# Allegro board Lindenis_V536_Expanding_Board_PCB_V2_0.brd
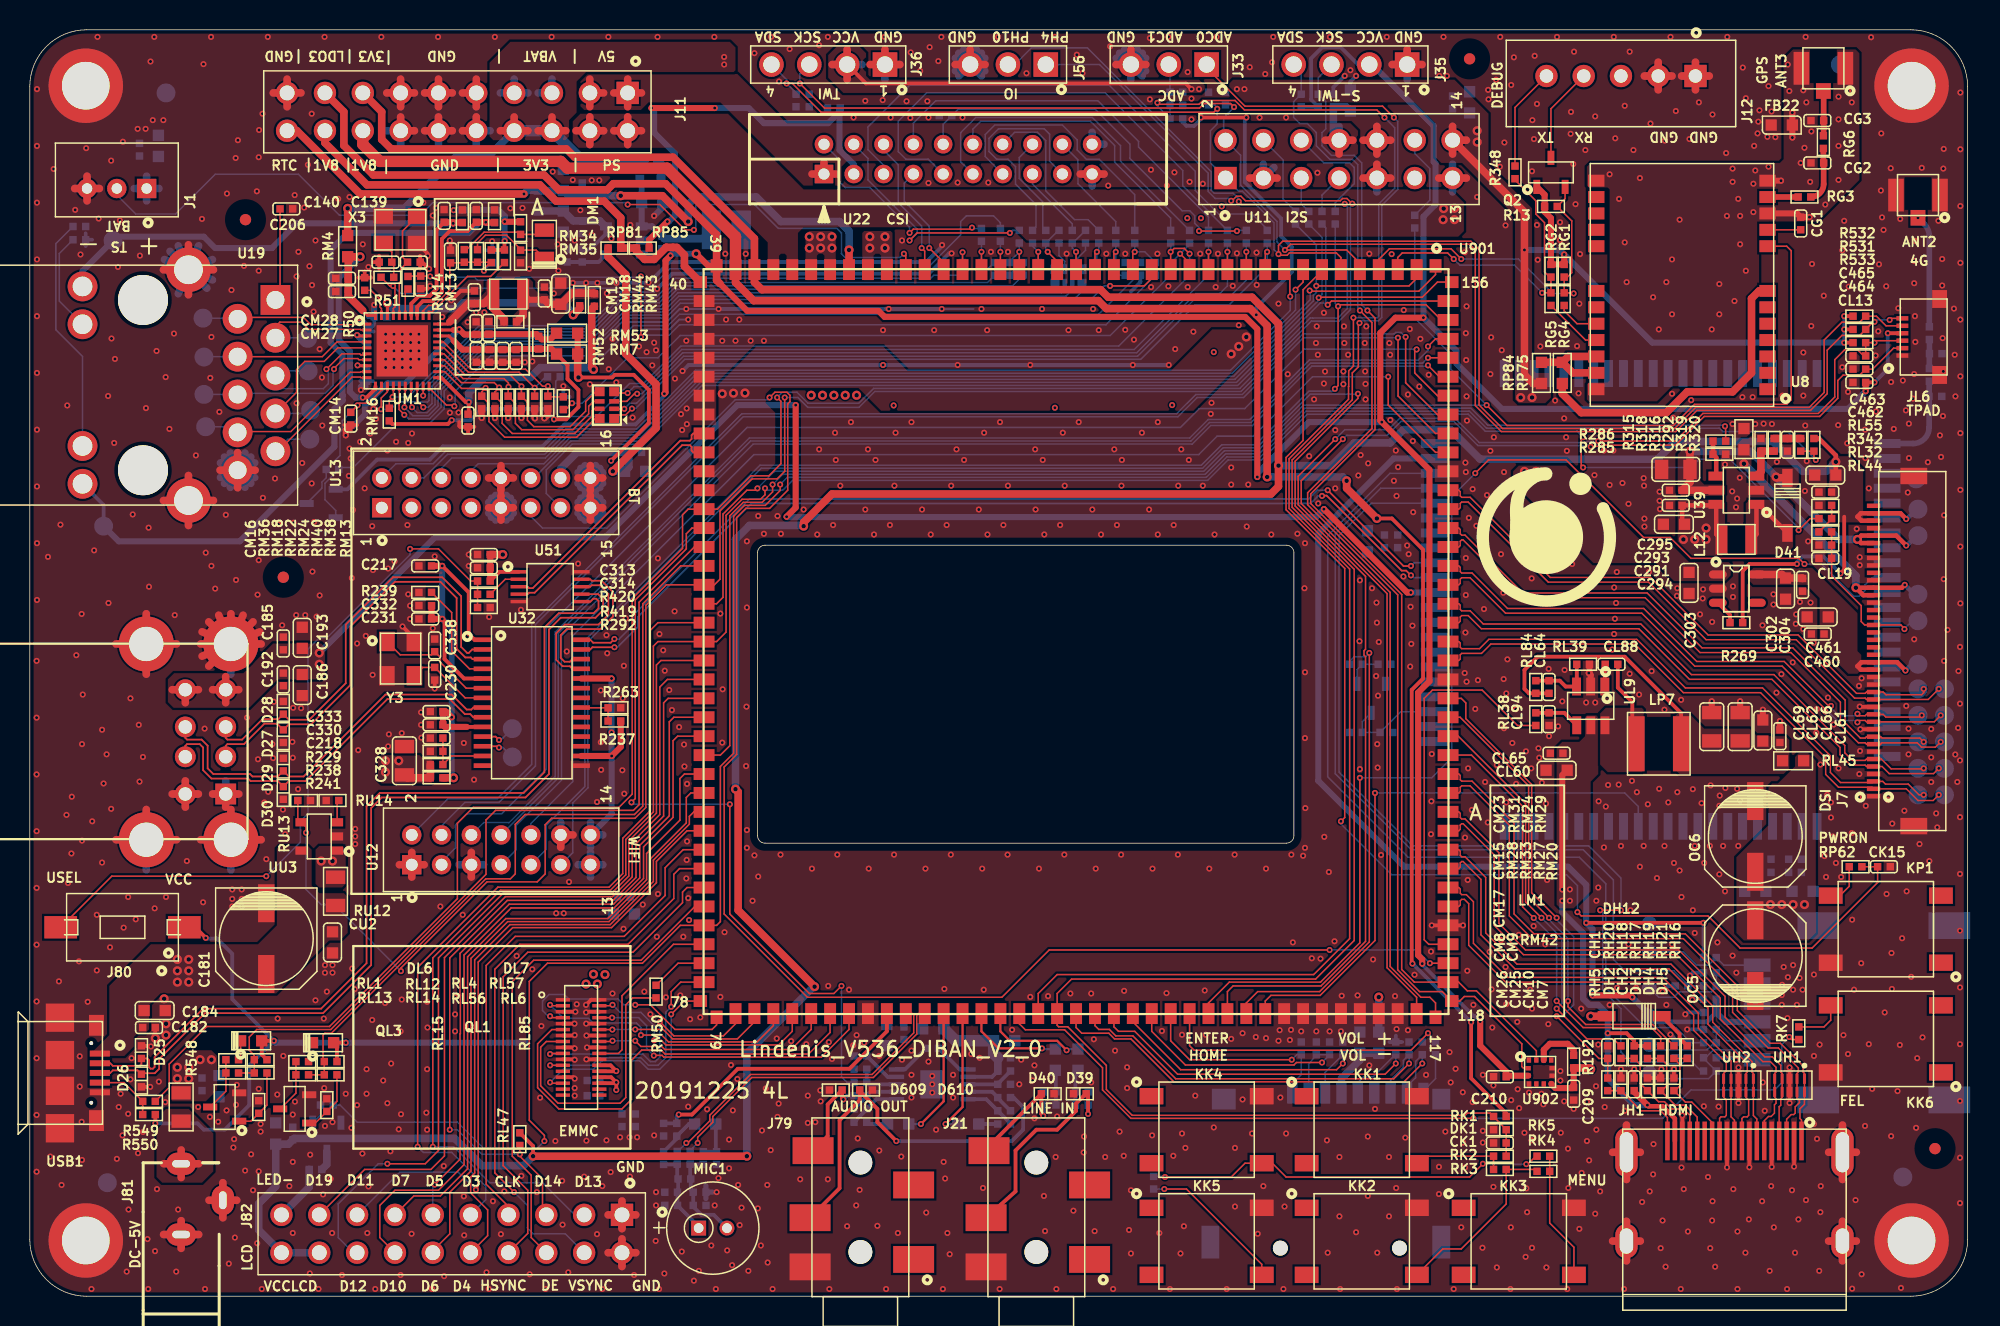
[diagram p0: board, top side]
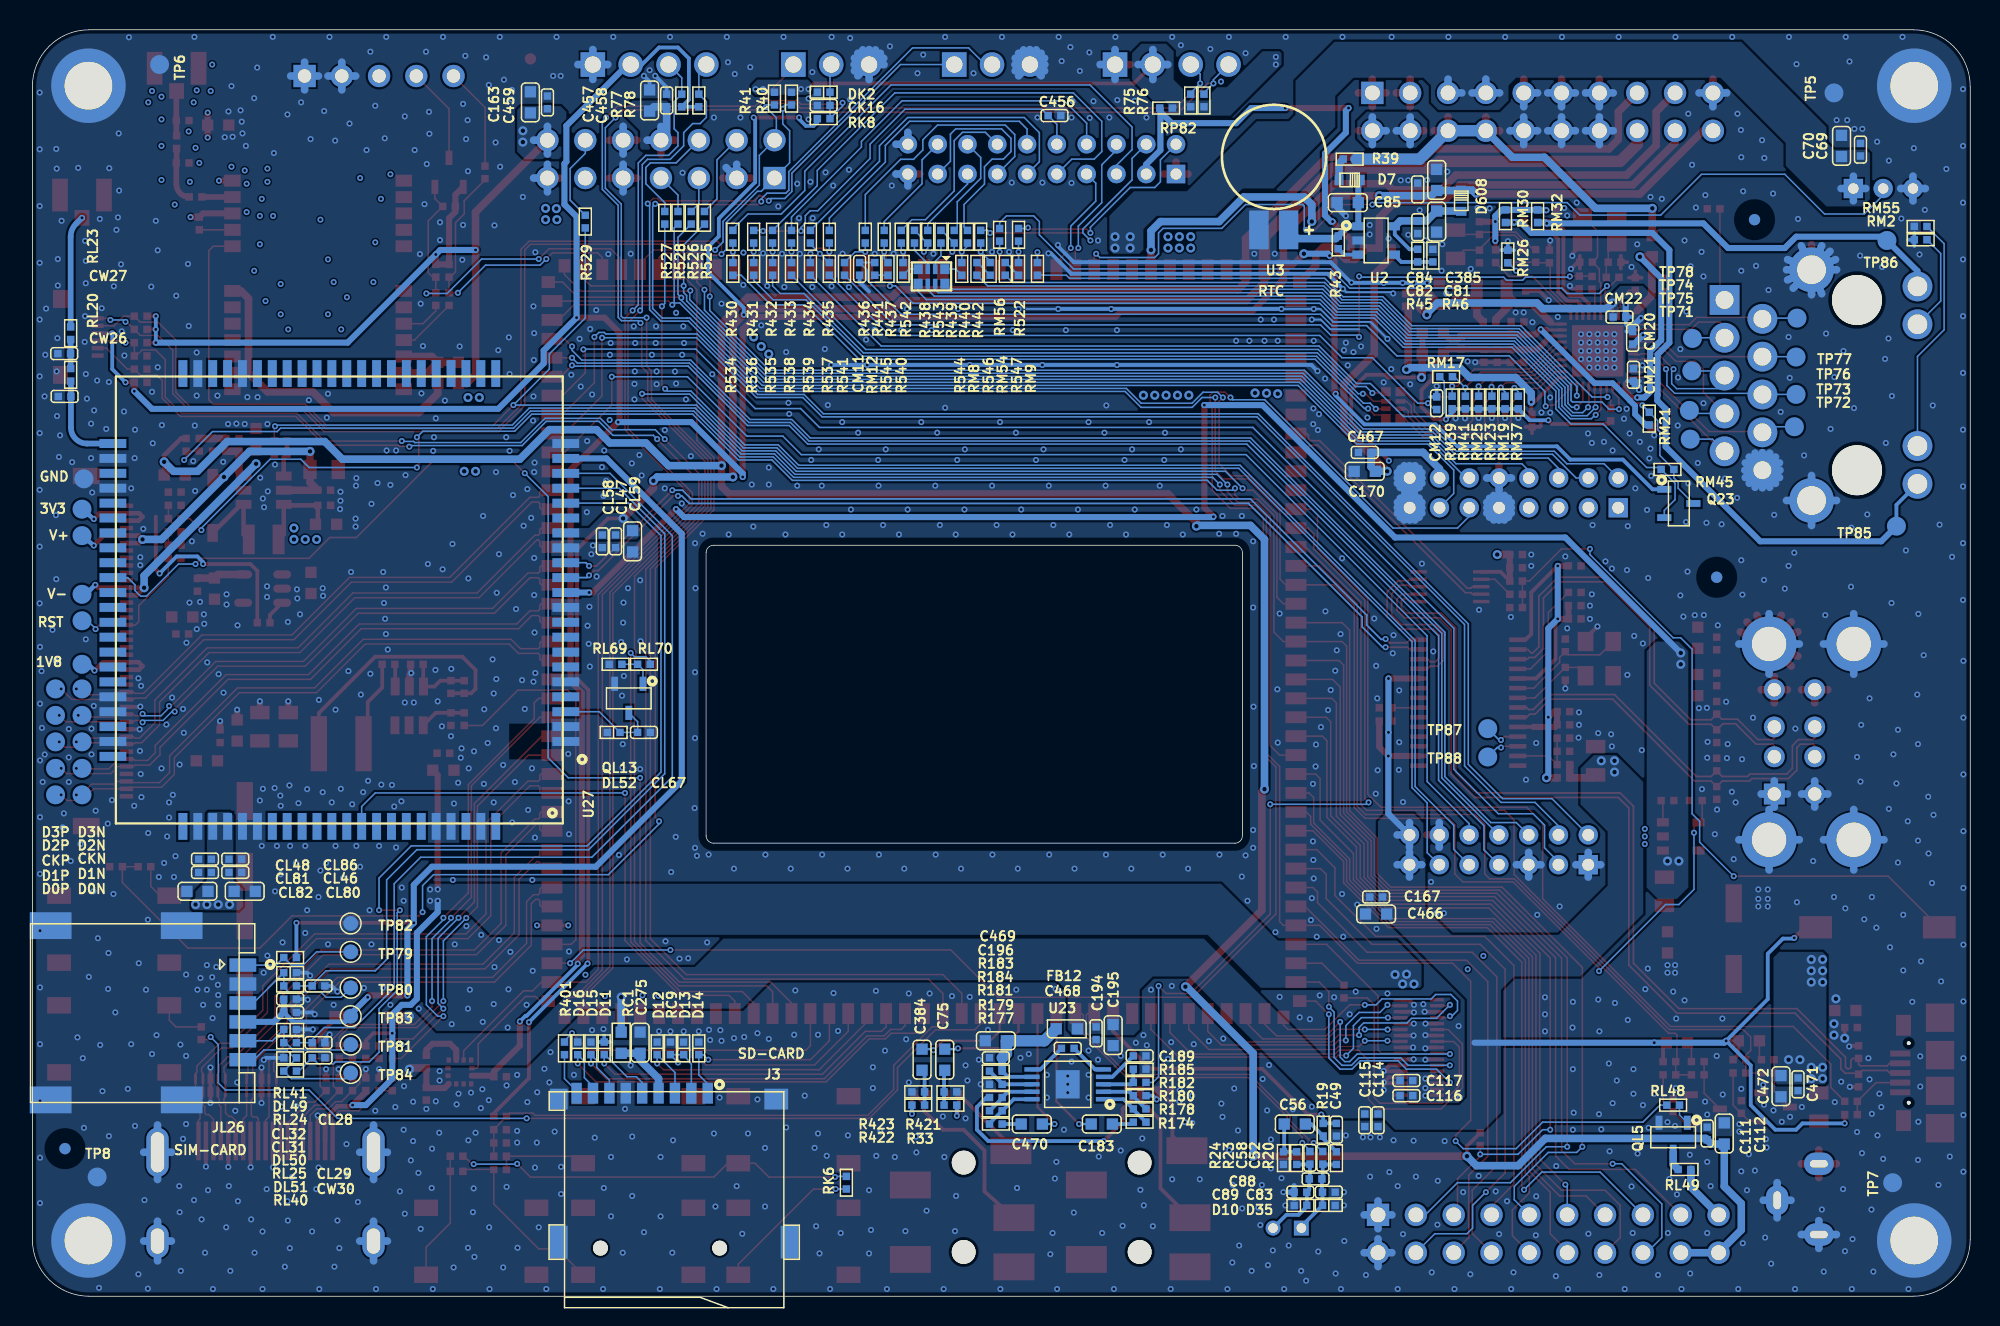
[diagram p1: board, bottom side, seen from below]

Outline 130.08 x 85.01 mm; copper layers: TOP, L2GND, L3SIG, BOTTOM. Coordinates in mm from the lower left corner of the outline.
Outline path: 0,81.2 0,3.81 arc(1.12,1.12) 3.81,0 126.27,0 arc(128.96,1.12) 130.08,3.81 130.08,81.2 arc(128.96,83.89) 126.27,85.01 3.81,85.01 arc(1.12,83.89) 0,81.2

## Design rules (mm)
net group CLKOUT-125M: nets CLKOUT-125M RGMII-CLKIN-125M#
net group D1_USB: nets USB1_DM USB1_DP
net group HTX: nets HTXCN HTXCP
net group HTX0: nets HTX0N HTX0P
net group HTX1: nets HTX1N HTX1P
net group HTX2: nets HTX2N HTX2P
net group MDI0: nets MDI0+ MDI0-
net group MDI1: nets MDI1+ MDI1-
net group MDI2: nets MDI2+ MDI2-
net group MDI3: nets MDI3+ MDI3-
net group MIC1-MIC: nets MIC1N-MIC MIC1P-MIC
net group MICIN1: nets MICIN1N MICIN1P
net group MICRO-USB0: nets MICRO-USB0-DM MICRO-USB0-DP
net group MIPI-DSI-CK: nets MIPI-DSI-CKN MIPI-DSI-CKP
net group MIPI-DSI-D0: nets MIPI-DSI-D0N MIPI-DSI-D0P
net group MIPI-DSI-D1: nets MIPI-DSI-D1N MIPI-DSI-D1P
net group MIPI-DSI-D2: nets MIPI-DSI-D2N MIPI-DSI-D2P
net group MIPI-DSI-D3: nets MIPI-DSI-D3N MIPI-DSI-D3P
net group USB-D1: nets USB1-DM USB1-DP
net group USB_D1: nets DM1_USB DP1_USB
net group USB_D2: nets DM2_USB DP2_USB
net group USB_D3: nets DM3_USB DP3_USB
net group USB_D4: nets DM4_USB DP4_USB
nets with their own width: min track width 0.254; nets ALDO1 ALDO3 VCC-3V3

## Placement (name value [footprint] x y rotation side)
ANT2  IPEX  [ANT3B300_310H125]  126.75 73.91 180 top
ANT3  GPS-ANT  [ANT3B300_310H125]  120.4 82.42 180 top
C49  2.2uF  [C0402]  42.55 11.18 270 bottom
C52  100nF  [C0402]  43.46 9.29 90 bottom
C56  4.7uF  [C0603]  45.34 11.56 180 bottom
C58  100nF  [C0402]  44.32 9.29 90 bottom
C69  104  [C0402]  7.37 76.96 270 bottom
C70  10uF  [C0603]  8.64 77.22 270 bottom
C75  4.7uF  [C0603]  68.83 15.88 270 bottom
C81  4.7uF  [C0603]  35.81 72.14 90 bottom
C82  104  [C0402]  37.08 71.75 90 bottom
C83  NC-33pF  [C0402]  43.05 6.99 180 bottom
C84  104  [C0402]  37.08 74.3 270 bottom
C85  4.7uF  [C0603]  41.78 73.41 180 bottom
C88  NC-100pF  [C0402]  43.94 7.87 180 bottom
C89  NC-33pF  [C0402]  44.96 6.99 180 bottom
C111  100nF  [C0402]  17.65 10.92 90 bottom
C112  10uF  [C0603]  16.51 10.92 90 bottom
C114  104  [C0402]  39.75 11.81 90 bottom
C115  104  [C0402]  40.64 11.81 90 bottom
C116  104  [C0402]  37.85 13.46 0 bottom
C117  104  [C0402]  37.85 14.48 0 bottom
C139  NC/10pF-NPO  [C0402]  25.78 69.41 180 top
C140  NC/10pF-NPO  [C0402]  23.88 69.41 0 top
C163  4.7uF  [C0603]  96.65 80.14 270 bottom
C167  104  [C0402]  39.88 26.8 0 bottom
C170  10uF  [C0603]  40.64 55.37 0 bottom
C181  220uF  [CA660H770]  15.88 24 90 top
C182  104  [C0402]  8 18.03 180 top
C183  NC/4.7uF  [C0603]  58.29 11.56 0 bottom
C184  10uF  [C0603]  8.38 19.18 180 top
C185  104  [C0402]  17.02 43.81 270 top
C186  10uF  [C0603]  18.29 41.02 90 top
C189  334  [C0402]  55.75 16.13 180 bottom
C192  104  [C0402]  17.02 41.4 90 top
C193  10uF  [C0603]  18.29 44.2 270 top
C194  104  [C0402]  58.67 17.65 270 bottom
C195  10uF  [C0603]  57.53 17.53 270 bottom
C196  104  [C0402]  65.41 16 0 bottom
C206  104  [C0402]  17.22 72.99 0 top
C209  104  [C0402]  103.63 13.59 90 top
C210  104  [C0402]  98.68 14.73 0 top
C217  0.1uF/10%/10V/0402  [C0402]  26.54 49.02 0 top
C218  0.1uF/10%/10V/0402  [C0402]  27.3 37.47 0 top
C230  20pF/10%/25V/0402  [C0402]  27.18 41.78 90 top
C231  0.1uF/10%/10V/0402  [C0402]  26.54 45.47 0 top
C275  10uF  [C0603]  89.28 17.02 270 bottom
C291  102  [C0402]  110.49 53.09 0 top
C292  1uF  [C0402]  117.98 57.15 90 top
C293  104-50V  [C0402]  110.49 54.1 0 top
C294  10uF  [C0603]  110.36 51.82 0 top
C295  10uF-50V  [C0805]  110.49 55.5 0 top
C302  4.7uF  [C0603]  117.86 47.5 90 top
C303  4.7uF  [C0603]  111.38 47.88 90 top
C304  104  [C0402]  119 47.75 90 top
C313  100nF  [C0402]  30.48 49.78 0 top
C314  2.2uF  [C0402]  30.48 48.9 0 top
C328  10uF/20%/10V/0805  [C0805]  25.15 35.94 90 top
C330  0.1uF/10%/10V/0402  [C0402]  27.3 38.35 0 top
C332  0.1uF/10%/10V/0402  [C0402]  26.54 46.35 0 top
C333  0.1uF/10%/10V/0402  [C0402]  27.3 39.24 0 top
C338  20pF/10%/25V/0402  [C0402]  27.18 43.69 90 top
C384  4.7uF  [C0603]  70.36 15.88 270 bottom
C385  10uF  [C0603]  35.81 74.93 270 bottom
C456  NC  [C0402]  61.47 79.25 180 bottom
C457  4.7uF  [C0603]  88.65 80.26 270 bottom
C458  104  [C0402]  87.5 80.26 270 bottom
C459  104  [C0402]  95.5 80.14 270 bottom
C460  104  [C0402]  120.02 44.45 0 top
C461  4.7uF  [C0603]  120.02 45.59 0 top
C462  104  [C0402]  120.52 53.98 0 top
C463  4.7uF  [C0603]  120.52 55.12 0 top
C464  NC/102  [C0402]  122.81 62.23 0 top
C465  102  [C0402]  122.81 63.12 0 top
C466  10uF  [C0603]  39.88 25.65 0 bottom
C467  104  [C0402]  40.64 56.64 0 bottom
C468  334  [C0402]  60.58 16.64 0 bottom
C469  10uF  [C0603]  65.41 17.14 0 bottom
C470  NC/4.7uF  [C0603]  62.99 11.56 0 bottom
C471  104  [C0402]  11.56 14.22 90 bottom
C472  10uF  [C0603]  12.7 14.1 90 bottom
CG1  10nF  [C0402]  118.87 72.01 270 top
CG2  NC  [C0402]  119.99 76.07 0 top
CG3  NC  [C0402]  119.99 78.92 0 top
CH1  104  [C0402]  105.92 16.38 90 top
CH2  104  [C0402]  107.7 14.22 90 top
CK1  102  [C0402]  98.68 10.29 0 top
CK15  104  [C0402]  124.46 28.83 0 top
CK16  102  [C0402]  76.96 79.93 180 bottom
CL13  100nF  [C0402]  122.81 61.34 180 top
CL19  NC-1uF  [C0402]  120.52 49.53 180 top
CL28  22pF  [C0402]  110.87 20.83 180 bottom
CL29  22pF  [C0402]  110.87 17.02 180 bottom
CL31  100nF  [C0402]  112.78 19.05 180 bottom
CL32  33pF  [C0402]  112.78 19.94 180 bottom
CL46  104  [C0402]  116.46 28.45 0 bottom
CL47  104  [C0402]  90.93 50.67 90 bottom
CL48  33pF  [C0402]  118.49 29.34 180 bottom
CL58  33pF  [C0402]  91.82 50.67 90 bottom
CL59  10uF  [C0603]  89.79 50.67 90 bottom
CL60  10uF-16V  [C0603]  102.49 35.31 180 top
CL61  104  [C0402]  117.47 37.59 90 top
CL62  22uF  [C0805]  114.81 38.23 90 top
CL64  NC-27pF  [C0402]  101.98 40.89 90 top
CL65  104-16V  [C0402]  102.49 36.45 180 top
CL66  10uF  [C0603]  116.33 37.97 90 top
CL67  104  [C0402]  89.03 37.85 180 bottom
CL69  22uF  [C0805]  112.9 38.23 90 top
CL80  10uF  [C0603]  115.82 27.18 0 bottom
CL81  104  [C0402]  118.49 28.45 180 bottom
CL82  10uF  [C0603]  119 27.18 180 bottom
CL86  33pF  [C0402]  116.46 29.34 0 bottom
CL88  104  [C0402]  106.17 42.42 0 top
CL94  104  [C0402]  101.98 38.73 270 top
CM7  104  [C0402]  32.64 63.12 90 top
CM8  104  [C0402]  29.96 64.98 270 top
CM9  104  [C0402]  30.81 65 270 top
CM10  4.7uF  [C0402]  31.75 63.12 90 top
CM11  NC-22pF  [C0402]  74.55 68.96 270 bottom
CM12  NC-22pF  [C0402]  35.81 59.94 90 bottom
CM13  22pF  [C0402]  26.24 68.05 270 top
CM14  104  [C0402]  21.54 58.91 270 top
CM15  NC-100pF  [C0402]  28.24 69.79 270 top
CM16  104  [C0402]  29.42 58.78 270 top
CM17  NC  [C0402]  29.84 67.06 270 top
CM18  10uF  [C0603]  35.64 67.29 270 top
CM19  104  [C0402]  34.54 67.31 90 top
CM20  104  [C0402]  22.66 64.33 90 bottom
CM21  104  [C0402]  22.61 61.85 270 bottom
CM22  104  [C0402]  23.55 65.73 180 bottom
CM23  NC-100pF  [C0402]  27.81 72.52 270 top
CM24  NC-100pF  [C0402]  29.97 72.52 270 top
CM25  NC-104  [C0402]  30.86 63.12 90 top
CM26  NC-104  [C0402]  29.97 63.12 90 top
CM27  104  [C0402]  20.95 67.44 0 top
CM28  104  [C0402]  20.95 68.33 0 top
CU2  2.2uF  [C0603]  20.32 23.75 90 top
CW26  NC  [C0402]  127.91 60.4 0 bottom
CW27  NC  [C0402]  127.94 63.27 0 bottom
CW30  22pF  [C0402]  110.87 16 180 bottom
D7  RB521S-30  [SOD80_120H80]  41.66 74.93 180 bottom
D10  NC-ESD5451X  [ESD0402]  44.96 6.1 180 bottom
D11  ESD9B5VL-2/TR  [ESD0402]  91.69 16.64 90 bottom
D12  ESD9B5VL-2/TR  [ESD0402]  88.14 16.64 90 bottom
D13  ESD9B5VL-2/TR  [ESD0402]  86.36 16.64 90 bottom
D14  ESD9B5VL-2/TR  [ESD0402]  85.34 16.64 90 bottom
D15  ESD9B5VL-2/TR  [ESD0402]  92.58 16.64 90 bottom
D16  ESD9B5VL-2/TR  [ESD0402]  93.47 16.64 90 bottom
D25  ESD9B5VL-2/TR  [ESD0402]  7.49 16.38 90 top
D26  ESD9B5VL-2/TR  [ESD0402]  7.49 14.48 270 top
D27  ESD9B5VL-2/TR  [ESD0402]  17.02 37.59 270 top
D28  ESD9B5VL-2/TR  [ESD0402]  17.02 39.5 90 top
D29  ESD9B5VL-2/TR  [ESD0402]  17.02 35.69 90 top
D30  ESD9B5VL-2/TR  [ESD0402]  17.02 33.78 270 top
D35  NC-ESD5451X  [ESD0402]  43.05 6.1 0 bottom
D39  ESD5451X-2-TR  [ESD0402]  70.48 13.59 0 top
D40  ESD5451X-2-TR  [ESD0402]  68.33 13.59 180 top
D41  1N5819HW-7-F  [SOD155_270H118]  117.98 53.09 90 top
D608  RB521S-30  [SOD80_120H80]  34.16 73.53 90 bottom
D609  ESD5451X  [ESD0402]  54.1 13.84 0 top
D610  ESD5451X  [ESD0402]  56.13 13.84 180 top
DH2  ESD5451X  [ESD0402]  106.81 14.22 90 top
DH3  ESD5451X  [ESD0402]  108.58 14.22 90 top
DH4  ESD5451X  [ESD0402]  109.47 14.22 90 top
DH5  ESD5451X  [ESD0402]  110.36 14.22 90 top
DH12  B5819W  [SOD155_270H118]  107.7 18.8 0 top
DK1  ESD9B5V-2/TR  [ESD0402]  98.68 11.18 0 top
DK2  ESD9B5V-2/TR  [ESD0402]  76.96 80.82 180 bottom
DL6  RED  [LED0603]  14.86 17.14 180 top
DL7  GREEN  [LED0603]  19.69 17.02 180 top
DL49  NC/ESD5451X  [ESD0402]  112.78 21.72 0 bottom
DL50  NC/ESD5451X  [ESD0402]  112.78 17.91 0 bottom
DL51  NC/ESD5451X  [ESD0402]  112.78 16 180 bottom
DL52  NC/ESD5451X  [ESD0402]  91.06 37.85 180 bottom
DM1  POWER  [LED0805]  34.54 70.61 270 top
FB12  0R  [L0603]  60.64 17.95 0 bottom
FB22  600R@100M-1A  [L0603]  117.6 78.61 180 top
J1  BATTARY  [HDR1_3P200B670_600H610]  5.84 74.93 180 top
J3  MICROSD/TF_SLOT  [SDC13B1450_1472H245]  87 6.48 0 bottom
J7  CON30-P05  [FPC42P50B450_2410H150_B]  126.36 43.31 90 top
J9  USB/A  [USB-2400-DIP]  6.73 37.21 270 top
J11  Header10x2  [HDR2_10P254B500_2540H254]  28.7 79.5 270 top
J12  XH2.54MM-5P-M  [HDR1_5P250B570_1500H700]  106.81 81.41 270 top
J21  PJ-327F  [HP5B650_1400H500]  67.56 5.97 180 top
J33  CON1X3-2.54-M  [HDR1_3P254B250_762H254]  76.45 82.68 180 top
J35  CON1X4-2.54-M  [HDR1_4P254B250_1016H254]  88.65 82.68 180 top
J36  CON1X4-2.54-M  [HDR1_4P254B250_1016H254]  53.59 82.68 180 top
J56  CON1X3-2.54-M  [HDR1_3P254B250_762H254]  65.66 82.68 180 top
J79  HP-JACK  [HP5B650_1400H500]  55.75 5.97 180 top
J80  SDA01H1SBD  [KEY2B452_749H445]  6.22 24.77 180 top
J81  DC-IN-JACK  [DC-208]  10.16 8.89 90 top
J82  Header10x2  [HDR2_10P254B500_2540H254]  28.32 4.19 270 top
JH1  HDMI_19plug type A  [HDMI23P50B1215_1500H838]  114.43 5.14 180 top
JL6  FPC-6P-0.5MM-B  [FPC8P50B320_500H150_B]  127.13 64.39 90 top
JL26  SIM508C  [SIM-6_1]  115.95 19.05 270 bottom
KK1  VOL+  [KEY4B620_620H430]  89.41 11.18 0 top
KK2  VOL-  [KEY4B620_620H430]  89.41 3.68 0 top
KK3  MENU  [KEY4B620_620H430]  99.95 3.68 0 top
KK4  ENTER  [KEY4B620_620H430]  78.99 11.18 0 top
KK5  HOME  [KEY4B620_620H430]  78.99 3.68 0 top
KK6  FEL  [KEY4B620_620H430]  124.59 17.27 180 top
KP1  PWRON  [KEY4B620_620H430]  124.59 24.64 180 top
L12  10uH_1A  [LP200_250H100]  114.55 50.8 0 top
LM1  2.2uH/1A DCR<0.1R  [LP200_250H100]  32.12 67.27 0 top
LP7  2.2uH@3A DCR<0.1R  [LP400_400H120]  109.35 37.08 0 top
MIC1  Micphone  [MIC2B600H500]  45.85 4.57 0 top
NOREF  -  [unnamed]  14.48 72.26 0 top
NOREF#2  -  [unnamed]  127.89 9.91 0 top
NOREF#3  -  [unnamed]  17.02 48.26 0 top
NOREF#4  -  [unnamed]  96.65 83.06 0 top
NOREF#5  -  [#2]  242.52 87.58 0 top
NOREF#6  -  [unnamed]  17.02 48.26 180 bottom
NOREF#7  -  [unnamed]  14.48 72.26 180 bottom
NOREF#8  -  [unnamed]  127.89 9.91 180 bottom
OC5  220uF/16V  [CA660H770]  115.82 22.86 270 top
OC6  220uF/16V  [CA660H770]  115.82 30.86 90 top
Q2  2N7002  [SOT3P95B130_290H103]  102.11 75.44 90 top
Q23  BSN20  [SOT3P95B130_290H103]  19.56 53.21 180 bottom
QL1  WNT2F04/MMBT3904  [SOT3P95B130_290H103]  17.78 12.57 180 top
QL3  MMBT3904  [SOT3P95B130_290H103]  13.08 12.7 180 top
QL5  MMBT3904  [SOT3P95B130_290H103]  19.94 10.67 270 bottom
QL13  MMBT3904  [SOT-23]  90.04 40.13 270 bottom
R13  10K  [R0402]  102.11 73.15 180 top
R19  1K  [R0402]  43.43 11.18 90 bottom
R20  1.5K  [R0402]  42.55 9.27 270 bottom
R23  1.5K  [R0402]  45.21 9.27 270 bottom
R24  1K  [R0402]  46.1 9.27 270 bottom
R33  4.7K  [R0402]  68.45 12.83 180 bottom
R39  1K  [R0402]  41.66 76.33 0 bottom
R40  NC-2K  [R0402]  79.12 80.39 270 bottom
R41  NC-2K  [R0402]  80.26 80.39 270 bottom
R43  10K  [R0402]  42.42 70.74 90 bottom
R45  62K-1%  [R0402]  37.08 69.85 90 bottom
R46  54.9K-1%  [R0402]  36.07 69.85 270 bottom
R50  2K49 1%  [R0402]  22.48 67.94 90 top
R51  NC/0R  [R0402]  24 68.4 180 top
R75  2K  [R0402]  52.32 80.26 270 bottom
R76  2K  [R0402]  51.43 80.26 270 bottom
R77  2K  [R0402]  86.49 80.26 270 bottom
R78  2K  [R0402]  85.34 80.26 270 bottom
R174  10K  [R0402]  55.75 11.68 0 bottom
R177  10K  [R0402]  65.41 11.56 0 bottom
R178  36K  [R0402]  55.75 12.57 180 bottom
R179  36K  [R0402]  65.41 12.45 0 bottom
R180  0R  [R0402]  55.75 13.46 180 bottom
R181  0R  [R0402]  65.41 13.34 180 bottom
R182  1K  [R0402]  55.75 14.35 180 bottom
R183  4K7  [R0402]  65.41 15.11 0 bottom
R184  3K3  [R0402]  65.41 14.22 180 bottom
R185  10K  [R0402]  55.75 15.24 180 bottom
R192  10K  [R0402]  103.63 15.75 90 top
R229  20K/0402  [R0402]  27.3 36.58 180 top
R237  10K/0402  [R0402]  39.24 38.61 180 top
R238  10K/0402  [R0402]  27.3 35.69 0 top
R239  680/0402  [R0402]  26.54 47.24 0 top
R241  0R/0402  [R0402]  27.3 34.8 180 top
R263  20K/0402  [R0402]  39.24 39.5 0 top
R269  10K  [R0402]  114.55 45.21 0 top
R285  10K  [R0402]  113.41 56.52 0 top
R286  0R  [R0402]  113.41 57.4 0 top
R292  1M  [R0402]  30.48 46.23 180 top
R315  2R7/1%  [R0603]  115.06 57.53 90 top
R316  20K  [R0402]  117.09 57.15 270 top
R318  2.7K  [R0402]  116.2 57.15 90 top
R319  4K7  [R0402]  118.87 57.15 90 top
R320  4K7  [R0402]  119.76 57.15 90 top
R342  0R  [R0402]  120.52 52.2 0 top
R348  1K  [R0402]  99.69 75.44 270 top
R401  1K  [R0402]  94.36 16.64 90 bottom
R419  1K  [R0402]  30.48 47.12 180 top
R420  NC/0R  [R0402]  30.48 48.01 0 top
R421  4.7K  [R0402]  68.45 13.72 180 bottom
R422  4.7K  [R0402]  70.61 12.83 0 bottom
R423  4.7K  [R0402]  70.61 13.72 0 bottom
R430  NC-0R  [R0402]  83.06 71.12 90 bottom
R431  NC-0R  [R0402]  81.66 71.12 90 bottom
R432  NC-0R  [R0402]  80.39 71.12 90 bottom
R433  NC-0R  [R0402]  79.12 71.12 90 bottom
R434  NC-0R  [R0402]  77.85 71.12 90 bottom
R435  NC-0R  [R0402]  76.58 71.12 90 bottom
R436  NC-0R  [R0402]  74.17 71.12 90 bottom
R437  NC-0R  [R0402]  71.75 71.12 90 bottom
R438  NC-0R  [R0402]  69.98 71.12 90 bottom
R439  NC-0R  [R0402]  68.2 71.12 90 bottom
R440  NC-0R  [R0402]  67.31 71.12 90 bottom
R441  NC-0R  [R0402]  72.9 71.12 90 bottom
R442  NC-0R  [R0402]  66.42 71.12 90 bottom
R522  NC-0R  [R0402]  63.88 71.25 90 bottom
R525  NC-0R  [R0402]  84.96 72.39 270 bottom
R526  NC-0R  [R0402]  85.85 72.39 270 bottom
R527  NC-0R  [R0402]  87.63 72.39 270 bottom
R528  NC-0R  [R0402]  86.74 72.39 270 bottom
R529  NC-0R  [R0402]  92.96 72.14 270 bottom
R531  10K  [R0402]  122.81 64.9 180 top
R532  10K  [R0402]  122.81 65.79 180 top
R533  10K  [R0402]  122.81 64.01 180 top
R534  0R  [R0402]  83.06 68.96 270 bottom
R535  0R  [R0402]  80.39 68.96 270 bottom
R536  0R  [R0402]  81.66 68.96 270 bottom
R537  0R  [R0402]  76.58 68.96 270 bottom
R538  0R  [R0402]  79.12 68.96 270 bottom
R539  0R  [R0402]  77.85 68.96 270 bottom
R540  0R  [R0402]  71.63 68.96 270 bottom
R541  0R  [R0402]  75.56 68.96 270 bottom
R542  0R  [R0402]  70.87 71.12 270 bottom
R543  0R  [R0402]  69.09 71.12 270 bottom
R544  0R  [R0402]  67.69 68.96 270 bottom
R545  0R  [R0402]  72.64 68.96 270 bottom
R546  0R  [R0402]  65.79 68.96 270 bottom
R547  0R  [R0402]  63.88 68.96 270 bottom
R548  0R  [R0805]  10.16 12.7 270 top
R549  1K  [R0402]  8 13.08 0 top
R550  1K  [R0402]  8 12.19 180 top
RC1  1R  [R0603]  90.55 17.02 270 bottom
RC9  NC-1M  [R0402]  87.25 16.64 90 bottom
RG1  10K  [R0402]  103 68.83 90 top
RG2  10K  [R0402]  102.11 68.83 90 top
RG3  0R  [R0402]  119.13 73.79 0 top
RG4  0R  [R0402]  103 66.93 270 top
RG5  0R  [R0402]  102.11 66.93 270 top
RG6  0R  [R0402]  120.4 77.47 90 top
RH5  1K  [R0402]  105.92 14.22 270 top
RH16  27K-1%  [R0402]  111.25 16.38 270 top
RH17  1.8K  [R0402]  108.58 16.38 270 top
RH18  1.8K  [R0402]  107.7 16.38 270 top
RH19  33R  [R0402]  109.47 16.38 270 top
RH20  33R  [R0402]  106.81 16.38 270 top
RH21  0R  [R0402]  110.36 16.38 270 top
RK1  100K-1%  [R0402]  98.68 12.06 0 top
RK2  6K8-1%  [R0402]  98.68 9.4 0 top
RK3  8K2-1%  [R0402]  98.68 8.51 180 top
RK4  10K-1%  [R0402]  101.6 8.38 180 top
RK5  11K-1%  [R0402]  101.6 9.4 0 top
RK6  13K-1%  [R0402]  75.44 7.62 90 bottom
RK7  50R  [R0402]  118.75 17.65 270 top
RK8  100K-1%  [R0402]  76.96 79.04 0 bottom
RL1  330R  [R0402]  13.59 15.88 0 top
RL4  150R  [R0402]  18.29 15.75 180 top
RL6  10K  [R0402]  20.19 14.86 180 top
RL12  NC-10K  [R0402]  15.49 15.88 180 top
RL13  NC-0R  [R0402]  13.59 14.99 0 top
RL14  10K  [R0402]  15.49 14.99 180 top
RL15  100K  [R0402]  15.37 12.7 90 top
RL20  0R  [R0402]  127.51 61.85 270 bottom
RL23  0R  [R0402]  127.51 64.64 270 bottom
RL24  22R  [R0402]  112.78 20.83 0 bottom
RL25  22R  [R0402]  112.78 17.02 0 bottom
RL32  10K  [R0402]  120.52 51.31 0 top
RL38  10K  [R0402]  101.09 38.73 270 top
RL39  2K2-1%  [R0402]  104.27 42.42 180 top
RL40  22R  [R0402]  112.78 15.11 180 bottom
RL41  0R  [R0402]  112.78 22.73 0 bottom
RL44  12K  [R0402]  120.52 50.42 0 top
RL45  0R  [R0603]  118.36 35.94 180 top
RL47  10K  [R0402]  32.89 10.54 90 top
RL48  4.7K  [R0402]  19.94 12.83 180 bottom
RL49  10R  [R0402]  19.18 8.51 180 bottom
RL55  1M  [R0402]  120.52 53.09 0 top
RL56  NC-0R  [R0402]  18.29 14.86 0 top
RL57  10K  [R0402]  20.19 15.75 180 top
RL69  47K  [R0402]  90.93 42.42 0 bottom
RL70  4K7  [R0402]  89.03 42.42 180 bottom
RL84  12K-1%  [R0402]  101.09 40.89 90 top
RL85  100K  [R0402]  19.94 12.83 90 top
RM2  510R  [R0402]  3.33 70.92 180 bottom
RM4  0R  [R0603]  21.34 70.48 90 top
RM5  0R*4  [RN0402]  69.72 68.45 0 bottom
RM7  NC-0R  [R0603]  36.07 63.25 0 top
RM8  0R  [R0402]  66.67 68.96 90 bottom
RM9  0R  [R0402]  62.61 68.96 90 bottom
RM12  0R  [R0402]  73.53 68.96 270 bottom
RM13  0R  [R0402]  35.81 59.94 270 top
RM14  0R  [R0402]  25.39 68.03 90 top
RM15  0R*4  [RN0402]  38.73 59.82 90 top
RM16  1K5  [R0402]  24.13 59.18 270 top
RM17  0R  [R0402]  35.18 61.72 0 bottom
RM18  4K7  [R0402]  31.22 59.99 270 top
RM19  NC-4K7  [R0402]  31.22 59.99 90 bottom
RM20  4K7  [R0402]  31.86 69.81 90 top
RM21  4K7  [R0402]  21.54 58.91 270 bottom
RM22  4K7  [R0402]  32.11 59.99 270 top
RM23  NC-4K7  [R0402]  32.11 59.99 90 bottom
RM24  NC/4K7  [R0402]  33 59.99 270 top
RM25  4K7  [R0402]  33 59.99 90 bottom
RM26  NC-4K7  [R0402]  31.04 69.79 90 bottom
RM27  4K7  [R0402]  30.97 69.81 270 top
RM28  NC-0R  [R0402]  29.16 69.83 270 top
RM29  4K7  [R0402]  31.2 72.5 90 top
RM30  NC-4K7  [R0402]  31.2 72.5 270 bottom
RM31  4K7  [R0402]  29.04 72.5 90 top
RM32  NC-4K7  [R0402]  29.04 72.5 270 bottom
RM33  0R  [R0402]  30.05 69.83 270 top
RM34  510R  [R0402]  32.94 71.7 270 top
RM35  NC-510R  [R0402]  32.94 69.79 270 top
RM36  NC-4K7  [R0402]  30.33 59.99 270 top
RM37  4K7  [R0402]  30.33 59.99 90 bottom
RM38  4K7  [R0402]  34.78 59.99 270 top
RM39  NC-4K7  [R0402]  34.78 59.99 90 bottom
RM40  4K7  [R0402]  33.89 59.99 270 top
RM41  NC-4K7  [R0402]  33.89 59.99 90 bottom
RM42  NC-0R  [R0402]  32.26 65.41 180 top
RM43  0R  [R0402]  37.9 66.87 90 top
RM44  0R  [R0402]  36.91 66.91 90 top
RM45  NC/0R  [R0402]  20.32 55.5 180 bottom
RM50  33R  [R0402]  42.04 20.45 270 top
RM52  0R  [R0402]  34.16 64.01 270 top
RM53  0R  [R0603]  36.07 64.64 0 top
RM54  0R  [R0402]  64.77 68.96 90 bottom
RM55  510R  [R0402]  3.33 71.81 180 bottom
RM56  0R  [R0402]  65.15 71.25 270 bottom
RP62  1K  [R0402]  122.55 28.83 0 top
RP75  0R  [R0603]  102.87 61.98 270 top
RP81  0R  [R0402]  39.24 70.36 0 top
RP82  0R  [R0402]  53.98 79.76 180 bottom
RP84  0R  [R0603]  101.47 61.98 270 top
RP85  NC/0R  [R0402]  41.15 70.36 180 top
RU12  NC-0R  [R0805]  20.52 27.18 90 top
RU13  100K  [R0402]  18.41 33.27 0 top
RU14  6.8K-1%  [R0402]  20.32 33.27 180 top
TP5  GND  [TP_PAD]  9.14 80.77 90 bottom
TP6  GND  [TP_PAD]  121.54 82.68 90 bottom
TP7  GND  [TP_PAD]  5.21 7.62 90 bottom
TP8  GND  [TP_PAD]  125.73 8 90 bottom
TP9  GND  [MH320CIR500D]  126.31 81.25 0 top
TP10  GND  [MH320CIR500D]  3.76 81.25 0 top
TP11  GND  [MH320CIR500D]  3.76 3.74 0 top
TP12  GND  [MH320CIR500D]  126.31 3.74 0 top
TP52  TEST POINT SURFACE  [TP_PAD]  126.75 33.66 90 bottom
TP53  TEST POINT SURFACE  [TP_PAD]  128.52 33.66 90 bottom
TP54  TEST POINT SURFACE  [TP_PAD]  126.75 35.43 90 bottom
TP55  TEST POINT SURFACE  [TP_PAD]  128.52 35.43 90 bottom
TP56  TEST POINT SURFACE  [TP_PAD]  126.75 37.21 90 bottom
TP57  TEST POINT SURFACE  [TP_PAD]  128.52 37.21 90 bottom
TP58  TEST POINT SURFACE  [TP_PAD]  126.75 38.99 90 bottom
TP59  TEST POINT SURFACE  [TP_PAD]  128.52 38.99 90 bottom
TP60  TEST POINT SURFACE  [TP_PAD]  126.75 40.77 90 bottom
TP61  TEST POINT SURFACE  [TP_PAD]  128.52 40.77 90 bottom
TP62  TEST POINT SURFACE  [TP_PAD]  126.62 54.86 90 bottom
TP63  TEST POINT SURFACE  [TP_PAD]  126.75 42.42 90 bottom
TP64  TEST POINT SURFACE  [TP_PAD]  126.75 47.12 90 bottom
TP65  TEST POINT SURFACE  [TP_PAD]  126.75 45.34 90 bottom
TP66  TEST POINT SURFACE  [TP_PAD]  126.75 52.83 90 bottom
TP67  TEST POINT SURFACE  [TP_PAD]  126.75 51.05 90 bottom
TP71  TEST POINT SURFACE  [TP_PAD]  18.8 57.53 0 bottom
TP72  TEST POINT SURFACE  [TP_PAD]  11.8 58.36 0 bottom
TP73  TEST POINT SURFACE  [TP_PAD]  11.69 60.53 0 bottom
TP74  TEST POINT SURFACE  [TP_PAD]  18.69 62.11 0 bottom
TP75  TEST POINT SURFACE  [TP_PAD]  18.85 59.46 0 bottom
TP76  TEST POINT SURFACE  [TP_PAD]  11.69 63.04 0 bottom
TP77  TEST POINT SURFACE  [TP_PAD]  11.63 65.65 0 bottom
TP78  TEST POINT SURFACE  [TP_PAD]  18.65 64.29 0 bottom
TP79  TDO  [TP100]  108.71 23.11 270 bottom
TP80  TDO  [TP100]  108.71 20.7 270 bottom
TP81  TDO  [TP100]  108.71 16.89 270 bottom
TP82  TDO  [TP100]  108.71 25.02 270 bottom
TP83  TDO  [TP100]  108.71 18.8 270 bottom
TP84  TDO  [TP100]  108.71 14.99 270 bottom
TP85  TEST POINT SURFACE  [TP_PAD]  4.95 51.69 180 bottom
TP86  TEST POINT SURFACE  [TP_PAD]  5.59 70.87 180 bottom
TP87  TEST POINT SURFACE  [TP_PAD]  32.38 38.1 180 bottom
TP88  TEST POINT SURFACE  [TP_PAD]  32.38 36.2 180 bottom
U2  AP2127k-ADJ  [SOT5P95B160_300H130]  39.88 70.87 180 bottom
U3  BAT  [CSE]  47.75 69.98 180 bottom
U8  NC-HDM1216D  [DFN24P110B1220_1600H270]  110.9 67.88 180 top
U11  2_54_16P  [HDR2_7P254]  87.88 76.33 90 top
U12  DIP14_2_0  [HDR2_7P2_00]  31.64 29.96 90 top
U13  DIP16_2_0  [HDR2_8P2_00]  30.63 53.93 90 top
U19  RMS-086C-10F0-GY  [RJ45-HFJ11-1G01E]  7.6 61.16 90 top
U22  CON 10x2 2.0mm  [IDC200-20]  59.31 76.33 180 top
U23  SMG8905  [SOP11P50B300_300H110]  60.58 14.22 0 bottom
U24  AP2127k-1.8  [SOT23-5]  114.55 47.5 0 top
U27  SIM7600C  [SUB_4G87B3000_3000H290]  109.47 46.74 0 bottom
U32  GL850G_SSOP28  [SOP28P65B530_1020H200]  33.7 39.84 0 top
U39  RT9293B20GJ6  [SOT6P95B160_290H145]  114.55 54.1 180 top
U51  SGM7227  [SOP10P50B300_300H110]  34.92 47.62 0 top
U901  V536_MODE  [V536_156PIN]  70.23 43.94 270 top
U902  BMA250  [QFN12P50B200_200H100]  101.38 15.05 0 top
UH1  AZ1345-04F  [RCLAMP0524P]  119.13 13.72 180 top
UH2  AZ1345-04F  [RCLAMP0524P]  115.7 13.72 180 top
UL9  SY8120B1ABC  [SOT6P95B180_310H100]  104.77 39.62 270 top
UM1  RTL8211F-CG  [QFN41P40B500_500H75]  25 63.46 0 top
UM2  GB042-34S-H10-Plug  [GB042-34P-H10-PLUG]  37.01 16.7 270 top
USB1  MIRCO_USB_5P  [USB9P65B495_740H235]  2.29 14.99 270 top
UU3  SY6280  [SOT5P95B160_300H130]  19.43 30.86 180 top
X3  NC/25M-12pF-20PPM  [X4B250_320H80_SMD]  24.88 71.59 270 top
Y3  12MHz/3225  [X4B250_320H80_SMD]  24.89 42.8 0 top

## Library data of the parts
ANT2 = ANT_0
ANT3 = SMA/RF_1
C49 C52 C56 C58 C83 C88 C89 C313 C314 = C-C0402
C69 C81 C82 C84 C85 C182-C186 C192 C193 C206 C275 C302-C304 C385 C470-C472 = CAPACITOR
C70 = CAPACITOR_0: room: POWER
C75 C384 CK15 CU2 = C-C0603
C111 C112 C114-C117 C139 C140 C163 C167 C170 C189 C194-C196 C209 C210 C291-C295 C456-C459 C466-C469 CH1 CH2 CL28 CL29 CL31 CL32 CL46-CL48 CL58 CL59 CL80-CL82 CL86 CM18 CW26 CW27 CW30 = CAPACITOR_0
C181 = CAPACITOR_POL_0: room: POWER
C217 C218 C230 C231 C328 C330 C332 C333 C338 = C
C460-C465 = CAPACITOR: room: POWER
CG1-CG3 CK1 CK16 CL13 CL19 CM11-CM14 CM16 CM19-CM22 = C-C0402: room: EMMC
CL60-CL62 CL64-CL67 CL69 CL88 CL94 = CAPACITOR_1
CM7-CM10 CM15 CM17 CM23-CM28 = CAP_2: room: EMAC
D7 = DIODE_SCHOTTKY_0
D10 D35 = ESD9B5VL
D11-D16 D25-D30 D609 D610 DH2-DH5 DL49-DL52 = 1_1.5KE100A
D39 D40 = ESD5451X
D41 = D_0
D608 = DIODE_SCHOTTKY_3
DH12 = DIO-B5819W
DK1 DK2 = TVS-FBP-02C
DL6 DL7 = LED_0
DM1 = LED_3
FB12 = INDUCTOR_4
FB22 = INDUCTOR: signal model: DEFAULT_INDUCTOR_0.001nH_1_2
J1 = CON3: room: POWER
J3 = SDMMC SLOT_0
J7 = CON40-B070EW01_0: room: LVDS
J9 = USB_A_4: Tolerance: #tol; User Part Number: xw
J11 J82 = Header10x2
J12 = XH2.54MM-5P-M
J21 = PJ-327F
J33 J56 = CON1X4-2_0.54-M
J35 J36 = CON1X4-2.54-M
J79 = HP_JACK
J80 = CON1X4-2_1.54-M
J81 = PHONEJack_DCIN_0
JH1 = HDMI19_PLUG
JL6 = FPC-6P-0_0.5MM-B
JL26 = SDMMC SLOT_5
KK1-KK6 = SWITCH_PUSH
KP1 = SW_PUSH_5
L12 = INDUCTOR
LM1 = L-LP2_00X1_60H1_00
LP7 = INDUCTOR_1
MIC1 = Micphone_0
OC5 OC6 = CAPACITOR_POL_0
Q2 = NMOS-2N7002
Q23 = NMOS-BSN20
QL1 QL3 QL13 = NPN
QL5 = NPN-MMBT3904
R13 R19 R20 R23 R24 R33 R40 R41 R75-R78 R292 R342 R348 R419-R423 R430-R442 R522 R525-R529 R534-R547 R549 R550 RC1 RC9 RH17-RH21 RM50 RU13 RU14 = R-R0402-5%
R39 R43 R45 R46 R50 R51 R174 R177-R185 R192 R229 R237-R239 R241 R263 R401 R531-R533 R548 RH5 RL1 RL4 RL6 RL12-RL15 RL20 RL23-RL25 RL38-RL41 RL45 RL56 RL57 RL84 RL85 RM4 RM7 RM16 RM18-RM27 RM29-RM32 RM36-RM41 RM45 RM52 RM53 RM56 = R
R269 RK1-RK8 RM2 RM8 RM9 RM12 RM13 RM17 RM28 RM33-RM35 RM42-RM44 RM54 RM55 = R-R0402: room: EMMC
R285 R286 R315 R316 R318-R320 RL69 RL70 = RESISTOR
RG1-RG6 = R: room: TCARD
RH16 = R-R0402-1%
RL32 RL44 RL47-RL49 RL55 = R-R0402-5%: room: EMMC
RM5 RM15 = R-PACK4_1
RM14 = R-R0402: room: EMMC; signal model: R-PACK4_1_RCA80-8_0R*4_0R*4
RP62 = R-R0402
RP75 RP84 = R-R0603-1%
RP81 RP82 RP85 = R-R0603-5%
RU12 = R-R0805-5%
TP5-TP12 TP52-TP67 TP71-TP88 = TEST POINT SURFACE
U2 U24 = uP0107_0
U3 = BAT_0
U8 = FEB1216
U11 = NAND_FLASH_TSOP48_9
U12 = HDR11X2_1
U13 = HDR11X2_2
U19 = HFJ11-1G01E_2
U22 = CON 10x2 2.0mm: User Part Number: pn
U23 = SSM2402/SO_2
U27 = AP1511B_2
U32 = GL850G_SSOP28
U39 = RT9293B
U51 = SGM7227
U901 = A10_MODE_20
U902 = BMA222
UH1 UH2 = rRClamp0524P
UL9 = SY8088_0
UM1 = RTL8169s_1
UM2 = NAND_FLASH_TSOP48_1: Tolerance: tol#; User Part Number: xw
USB1 = USB_MINI_SOCKET_0
UU3 = SY6280
X3 = CRYSTAL-4_0
Y3 = XTAL-4P

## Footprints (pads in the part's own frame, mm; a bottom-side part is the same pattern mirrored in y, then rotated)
ANT3B300_310H125
  rect 1.05x2.2 smd: 1(-1.475,0) 2(1.475,0)
  rect 1x1.05 smd: 3(0,1.525)
C0402
  rect 0.5x0.5 smd: 1(-0.425,0) 2(0.425,0)
C0603
  rect 0.76x0.76 smd: 1(-0.71,0) 2(0.71,0)
C0805
  rect 0.9x1.3 smd: 1(-0.95,0) 2(0.95,0)
CA660H770
  rect 2.55x1.1 smd: 1(-2.375,0) 2(2.375,0)
CSE
  rect 1.3x2.6 smd: 1(2,1.6) 2(0,1.6)
DC-208
  oval 1.5x2 hole 0.5x1.2: 1(0,0) 2(-4.75,0)
  oval 2x1.5 hole 1.2x0.5: 3(-2.45,-2.8)
DFN24P110B1220_1600H270
  rect 1.1x0.8 smd: 1(-5.75,7) 2(-5.75,5.9) 3(-5.75,4.8) 4(-5.75,3.7) 5(-5.75,2.6) 6(-5.75,1.5) 7(-5.75,0.4) 8(-5.75,-2.6) 9(-5.75,-3.7) 10(-5.75,-4.8) 11(-5.75,-5.9) 12(-5.75,-7) 13(5.75,-7) 14(5.75,-5.9) 15(5.75,-4.8) 16(5.75,-3.7) 17(5.75,-2.6) 18(5.75,0.4) 19(5.75,1.5) 20(5.75,2.6) 21(5.75,3.7) 22(5.75,4.8) 23(5.75,5.9) 24(5.75,7)
ESD0402
  rect 0.5x0.5 smd: 1(-0.425,0) 2(0.425,0)
FPC8P50B320_500H150_B
  rect 0.3x0.8 smd: 1(-1.25,1.43) 2(-0.75,1.43) 3(-0.25,1.43) 4(0.25,1.43) 5(0.75,1.43) 6(1.25,1.43)
  rect 1.2x1 smd: 7(2.55,-1.07) 8(-2.55,-1.07)
FPC42P50B450_2410H150_B
  rect 0.3x0.9 smd: 1(-9.75,2.6) 2(-9.25,2.6) 3(-8.75,2.6) 4(-8.25,2.6) 5(-7.75,2.6) 6(-7.25,2.6) 7(-6.75,2.6) 8(-6.25,2.6) 9(-5.75,2.6) 10(-5.25,2.6) 11(-4.75,2.6) 12(-4.25,2.6) 13(-3.75,2.6) 14(-3.25,2.6) 15(-2.75,2.6) 16(-2.25,2.6) 17(-1.75,2.6) 18(-1.25,2.6) 19(-0.75,2.6) 20(-0.25,2.6) 21(0.25,2.6) 22(0.75,2.6) 23(1.25,2.6) 24(1.75,2.6) 25(2.25,2.6) 26(2.75,2.6) 27(3.25,2.6) 28(3.75,2.6) 29(4.25,2.6) 30(4.75,2.6) 31(5.25,2.6) 32(5.75,2.6) 33(6.25,2.6) 34(6.75,2.6) 35(7.25,2.6) 36(7.75,2.6) 37(8.25,2.6) 38(8.75,2.6) 39(9.25,2.6) 40(9.75,2.6)
  rect 1.1x1.8 smd: 41(11.75,-0.1) 42(-11.75,-0.1)
GB042-34P-H10-PLUG
  rect 0.23x0.95 smd: 1(-3.2,-1.225) 2(-2.8,-1.225) 3(-2.4,-1.225) 4(-2,-1.225) 5(-1.6,-1.225) 6(-1.2,-1.225) 7(-0.8,-1.225) 8(-0.4,-1.225) 9(0,-1.225) 10(0.4,-1.225) 11(0.8,-1.225) 12(1.2,-1.225) 13(1.6,-1.225) 14(2,-1.225) 15(2.4,-1.225) 16(2.8,-1.225) 17(3.2,-1.225) 18(3.2,1.225) 19(2.8,1.225) 20(2.4,1.225) 21(2,1.225) 22(1.6,1.225) 23(1.2,1.225) 24(0.8,1.225) 25(0.4,1.225) 26(0,1.225) 27(-0.4,1.225) 28(-0.8,1.225) 29(-1.2,1.225) 30(-1.6,1.225) 31(-2,1.225) 32(-2.4,1.225) 33(-2.8,1.225) 34(-3.2,1.225)
HDMI23P50B1215_1500H838
  rect 0.3x2.6 smd: 1(-4.5,-5.285) 2(-4,-5.285) 3(-3.5,-5.285) 4(-3,-5.285) 5(-2.5,-5.285) 6(-2,-5.285) 7(-1.5,-5.285) 8(-1,-5.285) 9(-0.5,-5.285) 10(0,-5.285) 11(0.5,-5.285) 12(1,-5.285) 13(1.5,-5.285) 14(2,-5.285) 15(2.5,-5.285) 16(3,-5.285) 17(3.5,-5.285) 18(4,-5.285) 19(4.5,-5.285)
  oval 1.5x3.3 hole 0.9x2.7: 20(7.25,-4.525) 21(-7.25,-4.525)
  oval 1.5x2.3 hole 0.9x1.7: 22(7.25,1.435) 23(-7.25,1.435)
HDR1_3P200B670_600H610
  rect 1.3x1.3 hole 0.7: 1(-2,0.575)
  round 1.3 hole 0.7: 2(0,0.575) 3(2,0.575)
HDR1_3P254B250_762H254
  rect 1.65x1.65 hole 1.1: 1(-2.54,0)
  round 1.65 hole 1.1: 2(0,0) 3(2.54,0)
HDR1_4P254B250_1016H254
  rect 1.65x1.65 hole 1.1: 1(-3.81,0)
  round 1.65 hole 1.1: 2(-1.27,0) 3(1.27,0) 4(3.81,0)
HDR1_5P250B570_1500H700
  rect 1.5x1.5 hole 0.9: 1(-0.5,5)
  round 1.5 hole 0.9: 2(-0.5,2.5) 3(-0.5,0) 4(-0.5,-2.5) 5(-0.5,-5)
HDR2_7P2_00
  rect 1.3x1.3 hole 0.8: 1(-1,6)
  round 1.3 hole 0.8: 2(1,6) 3(-1,4) 4(1,4) 5(-1,2) 6(1,2) 7(-1,0) 8(1,0) 9(-1,-2) 10(1,-2) 11(-1,-4) 12(1,-4) 13(-1,-6) 14(1,-6)
HDR2_7P254
  rect 1.5x1.5 hole 1: 1(-1.27,7.62)
  round 1.5 hole 1: 2(1.27,7.62) 3(-1.27,5.08) 4(1.27,5.08) 5(-1.27,2.54) 6(1.27,2.54) 7(-1.27,0) 8(1.27,0) 9(-1.27,-2.54) 10(1.27,-2.54) 11(-1.27,-5.08) 12(1.27,-5.08) 13(-1.27,-7.62) 14(1.27,-7.62)
HDR2_8P2_00
  rect 1.3x1.3 hole 0.8: 1(-1,7)
  round 1.3 hole 0.8: 2(1,7) 3(-1,5) 4(1,5) 5(-1,3) 6(1,3) 7(-1,1) 8(1,1) 9(-1,-1) 10(1,-1) 11(-1,-3) 12(1,-3) 13(-1,-5) 14(1,-5) 15(-1,-7) 16(1,-7)
HDR2_10P254B500_2540H254
  rect 1.5x1.5 hole 1: 1(-1.27,11.43)
  round 1.5 hole 1: 2(1.27,11.43) 3(-1.27,8.89) 4(1.27,8.89) 5(-1.27,6.35) 6(1.27,6.35) 7(-1.27,3.81) 8(1.27,3.81) 9(-1.27,1.27) 10(1.27,1.27) 11(-1.27,-1.27) 12(1.27,-1.27) 13(-1.27,-3.81) 14(1.27,-3.81) 15(-1.27,-6.35) 16(1.27,-6.35) 17(-1.27,-8.89) 18(1.27,-8.89) 19(-1.27,-11.43) 20(1.27,-11.43)
HP5B650_1400H500
  round 1.6 hole 1.6 unplated: (0,3) (0,-3)
  rect 2.75x1.8 smd: 1(-3.575,3.5) 2(3.375,0.7) 3(-3.575,-1.5) 4(3.175,-3.8) 5(3.375,4)
IDC200-20
  rect 1.246x1.246 hole 0.75: 1(6,1)
  round 1.246 hole 0.75: 2(6,-1) 3(4,1) 4(4,-1) 5(2,1) 6(2,-1) 7(0,1) 8(0,-1) 9(-2,1) 10(-2,-1) 11(-4,1) 12(-4,-1) 13(-6,1) 14(-6,-1) 15(-8,1) 16(-8,-1) 17(-10,1) 18(-10,-1) 19(-12,1) 20(-12,-1)
KEY2B452_749H445
  rect 2.2x1.5 smd: 1(-4.15,0) 2(4.15,0)
KEY4B620_620H430
  rect 1.6x1.1 smd: 1(-3.7,2.25) 2(3.7,2.25) 3(-3.7,-2.25) 4(3.7,-2.25)
L0603
  rect 0.76x0.76 smd: 1(-0.71,0) 2(0.71,0)
LED0603
  rect 0.76x0.76 smd: 1(-0.71,0) 2(0.71,0)
LED0805
  rect 0.9x1.3 smd: 1(-0.95,0) 2(0.95,0)
LP200_250H100
  rect 0.8x2 smd: 1(-1,0) 2(1,0)
LP400_400H120
  rect 1.1x3.7 smd: 1(-1.5,0) 2(1.5,0)
MH320CIR500D
  round 5 hole 3.2: 1(0,0)
MIC2B600H500
  rect 1x1 hole 0.65: 1(-0.95,0)
  round 1 hole 0.65: 2(0.95,0)
QFN12P50B200_200H100
  rect 0.3x0.35 smd: 1(-0.75,0.8) 4(-0.75,-0.8) 5(-0.25,-0.8) 6(0.25,-0.8) 7(0.75,-0.8) 10(0.75,0.8) 11(0.25,0.8) 12(-0.25,0.8)
  rect 0.35x0.3 smd: 2(-0.8,0.25) 3(-0.8,-0.25) 8(0.8,-0.25) 9(0.8,0.25)
QFN41P40B500_500H75
  rect 0.63x0.2 smd: 1(-2.385,1.8) 2(-2.385,1.4) 3(-2.385,1) 4(-2.385,0.6) 5(-2.385,0.2) 6(-2.385,-0.2) 7(-2.385,-0.6) 8(-2.385,-1) 9(-2.385,-1.4) 10(-2.385,-1.8) 21(2.385,-1.8) 22(2.385,-1.4) 23(2.385,-1) 24(2.385,-0.6) 25(2.385,-0.2) 26(2.385,0.2) 27(2.385,0.6) 28(2.385,1) 29(2.385,1.4) 30(2.385,1.8)
  rect 0.2x0.63 smd: 11(-1.8,-2.385) 12(-1.4,-2.385) 13(-1,-2.385) 14(-0.6,-2.385) 15(-0.2,-2.385) 16(0.2,-2.385) 17(0.6,-2.385) 18(1,-2.385) 19(1.4,-2.385) 20(1.8,-2.385) 31(1.8,2.385) 32(1.4,2.385) 33(1,2.385) 34(0.6,2.385) 35(0.2,2.385) 36(-0.2,2.385) 37(-0.6,2.385) 38(-1,2.385) 39(-1.4,2.385) 40(-1.8,2.385)
  rect 3.45x3.45 smd: 41(0,0)
R0402
  rect 0.5x0.5 smd: 1(-0.425,0) 2(0.425,0)
R0603
  rect 0.76x0.76 smd: 1(-0.71,0) 2(0.71,0)
R0805
  rect 0.9x1.3 smd: 1(-0.95,0) 2(0.95,0)
RCLAMP0524P
  rect 0.2x0.675 smd: 1(0,-0.875) 2(0.5,-0.875) 4(1.5,-0.875) 5(2,-0.875) 6(2,0) 7(1.5,0) 9(0.5,0) 10(0,0)
  rect 0.4x0.67 smd: 3(1,-0.875) 8(1,0)
RJ45-HFJ11-1G01E
  round 3.35 hole 3.35 unplated: (-5.715,0) (5.715,0)
  rect 2x2 hole 1.2: 1(5.72,-8.89)
  round 2 hole 1.2: 2(4.45,-6.35) 3(3.18,-8.89) 4(1.91,-6.35) 5(0.64,-8.89) 6(-0.63,-6.35) 7(-1.9,-8.89) 8(-3.17,-6.35) 9(-4.44,-8.89) 10(-5.71,-6.35)
  round 2 hole 1.32: 11(6.625,4.06) 12(4.085,4.06) 13(-4.085,4.06) 14(-6.625,4.06)
  round 3 hole 1.93: 15(7.745,-3.05) 16(-7.745,-3.05)
RN0402
  rect 0.61x0.66 smd: 1(-0.9,-0.486) 4(0.9,-0.486) 5(0.9,0.486) 8(-0.9,0.486)
  rect 0.305x0.66 smd: 2(-0.25,-0.486) 3(0.25,-0.486) 6(0.25,0.486) 7(-0.25,0.486)
SDC13B1450_1472H245
  round 1 hole 1 unplated: (-3.05,3.25) (4.95,3.25)
  rect 0.7x1.4 smd: 1(-2.25,-7.15) 2(-1.15,-7.15) 3(-0.05,-7.15) 4(1.05,-7.15) 5(2.15,-7.15) 6(3.25,-7.15) 7(4.35,-7.15) 8(5.45,-7.15) 9(6.55,-7.15)
  rect 1.2x1.4 smd: 10(7.75,-6.75)
  rect 1.6x1.4 smd: 11(-6.85,-6.75)
  rect 1.2x2.2 smd: 12(7.75,2.85) 13(-7.75,2.85)
SIM-6_1
  rect 1.8x2.8 smd: 7(5.875,-4.1) 8(5.875,-12.9) 9(-5.825,-12.9) 10(-5.825,-4.1)
  rect 0.9x1.8 smd: C1(-3.175,0) C2(-0.635,0) C3(1.905,0) C5(-1.905,0) C6(0.635,0) C7(3.175,0)
SOD80_120H80
  rect 0.6x0.7 smd: 1(-0.71,0) 2(0.71,0)
SOD155_270H118
  rect 1.2x0.7 smd: 1(-1.85,0) 2(1.85,0)
SOP10P50B300_300H110
  rect 1.1x0.23 smd: 1(-2.1,1) 2(-2.1,0.5) 3(-2.1,0) 4(-2.1,-0.5) 5(-2.1,-1) 6(2.1,-1) 7(2.1,-0.5) 8(2.1,0) 9(2.1,0.5) 10(2.1,1)
SOP11P50B300_300H110
  rect 1.02x0.3 smd: 1(-2.4,1) 2(-2.4,0.5) 3(-2.4,0) 4(-2.4,-0.5) 5(-2.4,-1) 6(2.4,-1) 7(2.4,-0.5) 8(2.4,0) 9(2.4,0.5) 10(2.4,1)
  rect 1.6x1.9 smd: 11(0,0)
SOP28P65B530_1020H200
  rect 1.15x0.31 smd: 1(-3.325,4.225) 2(-3.325,3.575) 3(-3.325,2.925) 4(-3.325,2.275) 5(-3.325,1.625) 6(-3.325,0.975) 7(-3.325,0.325) 8(-3.325,-0.325) 9(-3.325,-0.975) 10(-3.325,-1.625) 11(-3.325,-2.275) 12(-3.325,-2.925) 13(-3.325,-3.575) 14(-3.325,-4.225) 15(3.325,-4.225) 16(3.325,-3.575) 17(3.325,-2.925) 18(3.325,-2.275) 19(3.325,-1.625) 20(3.325,-0.975) 21(3.325,-0.325) 22(3.325,0.325) 23(3.325,0.975) 24(3.325,1.625) 25(3.325,2.275) 26(3.325,2.925) 27(3.325,3.575) 28(3.325,4.225)
SOT3P95B130_290H103
  rect 0.95x0.46 smd: 1(-0.975,0.95) 2(-0.975,-0.95) 3(0.975,0)
SOT5P95B160_300H130
  rect 0.8x0.55 smd: 1(-1.2,0.95) 2(-1.2,0) 3(-1.2,-0.95) 4(1.2,-0.95) 5(1.2,0.95)
SOT6P95B160_290H145
  rect 1.05x0.6 smd: 1(-1.35,0.95) 2(-1.35,0) 3(-1.35,-0.95) 4(1.35,-0.95) 5(1.35,0) 6(1.35,0.95)
SOT6P95B180_310H100
  rect 1.2x0.6 smd: 1(-1.3,0.95) 2(-1.3,0) 3(-1.3,-0.95) 4(1.3,-0.936) 5(1.3,0.014) 6(1.3,0.964)
SOT23-5
  oval 1.2x0.55 smd: 1(-1.246,0.95) 2(-1.246,0) 3(-1.246,-0.95) 4(1.373,-0.95) 5(1.373,0.95)
SOT-23
  rect 0.95x0.46 smd: 1(-0.975,0.95) 2(-0.975,-0.95) 3(0.975,0)
SUB_4G87B3000_3000H290
  rect 1.8x0.6 smd: 1(-15.2,9.5) 2(-15.2,8.5) 3(-15.2,7.5) 4(-15.2,6.5) 5(-15.2,5.5) 6(-15.2,4.5) 7(-15.2,3.5) 8(-15.2,2.5) 9(-15.2,1.5) 10(-15.2,0.5) 11(-15.2,-0.5) 12(-15.2,-1.5) 13(-15.2,-2.5) 14(-15.2,-3.5) 15(-15.2,-4.5) 16(-15.2,-5.5) 17(-15.2,-6.5) 18(-15.2,-7.5) 19(-15.2,-8.5) 20(-15.2,-9.5) 41(15.2,-9.5) 42(15.2,-8.5) 43(15.2,-7.5) 44(15.2,-6.5) 45(15.2,-5.5) 46(15.2,-4.5) 47(15.2,-3.5) 48(15.2,-2.5) 49(15.2,-1.5) 50(15.2,-0.5) 51(15.2,0.5) 52(15.2,1.5) 53(15.2,2.5) 54(15.2,3.5) 55(15.2,4.5) 56(15.2,5.5) 57(15.2,6.5) 58(15.2,7.5) 59(15.2,8.5) 60(15.2,9.5) 81(-15.2,-10.5) 82(15.2,-10.5) 85(15.2,10.5)
  rect 0.6x1.8 smd: 21(-9.5,-15.2) 22(-8.5,-15.2) 23(-7.5,-15.2) 24(-6.5,-15.2) 25(-5.5,-15.2) 26(-4.5,-15.2) 27(-3.5,-15.2) 28(-2.5,-15.2) 29(-1.5,-15.2) 30(-0.5,-15.2) 31(0.5,-15.2) 32(1.5,-15.2) 33(2.5,-15.2) 34(3.5,-15.2) 35(4.5,-15.2) 36(5.5,-15.2) 37(6.5,-15.2) 38(7.5,-15.2) 39(8.5,-15.2) 40(9.5,-15.2) 61(9.5,15.2) 62(8.5,15.2) 63(7.5,15.2) 64(6.5,15.2) 65(5.5,15.2) 66(4.5,15.2) 67(3.5,15.2) 68(2.5,15.2) 69(1.5,15.2) 70(0.5,15.2) 71(-0.5,15.2) 72(-1.5,15.2) 73(-2.5,15.2) 74(-3.5,15.2) 75(-4.5,15.2) 76(-5.5,15.2) 77(-6.5,15.2) 78(-7.5,15.2) 79(-8.5,15.2) 80(-9.5,15.2) 83(10.5,-15.2) 84(-10.5,-15.2) 86(-10.5,15.2) 87(10.5,15.2)
TP100
  round 1 smd: 1(0,0)
TP_PAD
  round 1.27 smd: 1(0,0)
unnamed
  round 0.76 smd: (0,0)
USB9P65B495_740H235
  round 0.254 hole 0.6 unplated: (-2,1.84) (2,1.84)
  rect 0.4x1.35 smd: 1(-1.3,2.415) 2(-0.65,2.415) 3(0,2.415) 4(0.65,2.415) 5(1.3,2.415)
  rect 1.4x1 smd: 6(3.2,2.19) 9(-3.2,2.19)
  rect 1.9x1.9 smd: 7(3.71,-0.26) 8(-3.71,-0.26) 10(-1.2,-0.26) 11(1.2,-0.26)
USB-2400-DIP
  rect 1.4x1.4 hole 0.9: 1(3.5,6.418)
  round 1.4 hole 0.9: 2(1,6.418) 3(-1,6.418) 4(-3.5,6.418) 5(3.5,3.708) 6(1,3.708) 7(-1,3.708) 8(-3.5,3.708)
  round 3.7 hole 2.3: 9(-6.57,6.768) 10(6.57,6.768) 11(-6.57,1.088) 12(6.57,1.088)
V536_156PIN
  rect 0.9x0.8 smd: 1(-25.22,24.13) 39(-25.22,-24.13) 79(25.22,-24.13) 117(25.22,24.13)
  rect 1.4x0.8 smd: 2(-24.97,22.86) 3(-24.97,21.59) 4(-24.97,20.32) 5(-24.97,19.05) 6(-24.97,17.78) 7(-24.97,16.51) 8(-24.97,15.24) 9(-24.97,13.97) 10(-24.97,12.7) 11(-24.97,11.43) 12(-24.97,10.16) 13(-24.97,8.89) 14(-24.97,7.62) 15(-24.97,6.35) 16(-24.97,5.08) 17(-24.97,3.81) 18(-24.97,2.54) 19(-24.97,1.27) 20(-24.97,0) 21(-24.97,-1.27) 22(-24.97,-2.54) 23(-24.97,-3.81) 24(-24.97,-5.08) 25(-24.97,-6.35) 26(-24.97,-7.62) 27(-24.97,-8.89) 28(-24.97,-10.16) 29(-24.97,-11.43) 30(-24.97,-12.7) 31(-24.97,-13.97) 32(-24.97,-15.24) 33(-24.97,-16.51) 34(-24.97,-17.78) 35(-24.97,-19.05) 36(-24.97,-20.32) 37(-24.97,-21.59) 38(-24.97,-22.86) 80(24.97,-22.86) 81(24.97,-21.59) 82(24.97,-20.32) 83(24.97,-19.05) 84(24.97,-17.78) 85(24.97,-16.51) 86(24.97,-15.24) 87(24.97,-13.97) 88(24.97,-12.7) 89(24.97,-11.43) 90(24.97,-10.16) 91(24.97,-8.89) 92(24.97,-7.62) 93(24.97,-6.35) 94(24.97,-5.08) 95(24.97,-3.81) 96(24.97,-2.54) 97(24.97,-1.27) 98(24.97,0) 99(24.97,1.27) 100(24.97,2.54) 101(24.97,3.81) 102(24.97,5.08) 103(24.97,6.35) 104(24.97,7.62) 105(24.97,8.89) 106(24.97,10.16) 107(24.97,11.43) 108(24.97,12.7) 109(24.97,13.97) 110(24.97,15.24) 111(24.97,16.51) 112(24.97,17.78) 113(24.97,19.05) 114(24.97,20.32) 115(24.97,21.59) 116(24.97,22.86)
  rect 0.8x0.9 smd: 40(-24.13,-25.22) 78(24.13,-25.22) 118(24.13,25.22) 156(-24.13,25.22)
  rect 0.8x1.4 smd: 41(-22.86,-24.97) 42(-21.59,-24.97) 43(-20.32,-24.97) 44(-19.05,-24.97) 45(-17.78,-24.97) 46(-16.51,-24.97) 47(-15.24,-24.97) 48(-13.97,-24.97) 49(-12.7,-24.97) 50(-11.43,-24.97) 51(-10.16,-24.97) 52(-8.89,-24.97) 53(-7.62,-24.97) 54(-6.35,-24.97) 55(-5.08,-24.97) 56(-3.81,-24.97) 57(-2.54,-24.97) 58(-1.27,-24.97) 59(0,-24.97) 60(1.27,-24.97) 61(2.54,-24.97) 62(3.81,-24.97) 63(5.08,-24.97) 64(6.35,-24.97) 65(7.62,-24.97) 66(8.89,-24.97) 67(10.16,-24.97) 68(11.43,-24.97) 69(12.7,-24.97) 70(13.97,-24.97) 71(15.24,-24.97) 72(16.51,-24.97) 73(17.78,-24.97) 74(19.05,-24.97) 75(20.32,-24.97) 76(21.59,-24.97) 77(22.86,-24.97) 119(22.86,24.97) 120(21.59,24.97) 121(20.32,24.97) 122(19.05,24.97) 123(17.78,24.97) 124(16.51,24.97) 125(15.24,24.97) 126(13.97,24.97) 127(12.7,24.97) 128(11.43,24.97) 129(10.16,24.97) 130(8.89,24.97) 131(7.62,24.97) 132(6.35,24.97) 133(5.08,24.97) 134(3.81,24.97) 135(2.54,24.97) 136(1.27,24.97) 137(0,24.97) 138(-1.27,24.97) 139(-2.54,24.97) 140(-3.81,24.97) 141(-5.08,24.97) 142(-6.35,24.97) 143(-7.62,24.97) 144(-8.89,24.97) 145(-10.16,24.97) 146(-11.43,24.97) 147(-12.7,24.97) 148(-13.97,24.97) 149(-15.24,24.97) 150(-16.51,24.97) 151(-17.78,24.97) 152(-19.05,24.97) 153(-20.32,24.97) 154(-21.59,24.97) 155(-22.86,24.97)
X4B250_320H80_SMD
  rect 1.05x1.3 smd: 1(-0.925,1.15) 2(-0.925,-1.15) 3(0.925,-1.15) 4(0.925,1.15)

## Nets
3V3-STBY: RP75.1 RP84.1 U8.22(AVD33BAK) U8.23(AVD33DC)
AVDD1: C217.2 C231.2 C330.2 C332.2 C333.2 R241.1 U32.1(AVDD1) U32.5(AVDD2) U32.10(AVDD3)
AVDD10: CM20.1 CM21.1 CM22.1 RM44.1 UM1.3(AVDD10 3) UM1.8(AVDD10 8) UM1.38(AVDD10 38)
AVDD33: CM27.2 CM28.2 RM4.1 UM1.11(AVDD33 11) UM1.40(AVDD33 40)
DVDD10: CM16.1 RM43.1 UM1.21(DVDD10 21)
DVDD33: CM8.2 CM9.2 RM20.2 RM21.2 RM27.1 RM30.1 RM32.1 RM34.1 RM52.1 RM53.1 UM1.29(DVDD33 29)
DVDDRG: CM7.2 CM10.2 CM25.2 CM26.2 RM7.1 RM16.2 RM19.1 RM23.1 RM25.1 RM37.1 RM39.1 RM41.1 RM52.2 UM1.28(DVDD_RG)
GND: ANT2.1 ANT2.2 C49.2 C69.1 C70.1 C81.1 C82.1 C83.2 C84.1 C85.1 C89.1 C111.2 C112.2 C114.1 C115.1 C116.1 C117.1 C139.1 C140.1 C163.1 C167.2 C170.2 C181.2 C182.1 C184.1 C185.1 C186.1 C189.2 C192.1 C193.1 C194.2 C195.2 C196.2 C206.2 C209.1 C210.1 C217.1 C218.1 C230.1 C231.1 C275.1 C291.1 C292.1 C293.1 C294.1 C295.1 C302.1 C303.1 C304.1 C313.1 C314.1 C328.2 C330.1 C332.1 C333.1 C338.2 C385.1 C456.2 C457.1 C458.1 C459.1 C460.1 C461.1 C462.1 C463.1 C464.1 C465.1 C466.2 C467.2 C469.2 C471.1 C472.1 CH1.2 CH2.2 CK1.1 CK15.2 CK16.1 CL13.2 CL19.2 CL28.2 CL29.2 CL31.2 CL32.2 CL46.1 CL47.1 CL48.1 CL58.1 CL59.1 CL60.2 CL61.2 CL62.2 CL65.2 CL66.2 CL67.2 CL69.2 CL80.1 CL81.1 CL82.1 CL86.1 CL94.2 CM7.1 CM8.1 CM9.1 CM10.1 CM11.2 CM12.2 CM13.2 CM14.2 CM15.1 CM16.2 CM17.1 CM18.1 CM19.2 CM20.2 CM21.2 CM22.2 CM23.1 CM24.1 CM25.1 CM26.1 CM27.1 CM28.1 CU2.1 CW26.2 CW27.2 CW30.2 D10.1(ANODE) D11.2(CATHODE) D12.2(CATHODE) D13.2(CATHODE) D14.2(CATHODE) D15.2(CATHODE) D16.2(CATHODE) D25.2(CATHODE) D26.2(CATHODE) D27.2(CATHODE) D28.2(CATHODE) D29.2(CATHODE) D30.2(CATHODE) D35.1(ANODE) D39.1(ANODE) D40.1(ANODE) D609.1(ANODE) D610.1(ANODE) DH2.2(CATHODE) DH3.2(CATHODE) DH4.2(CATHODE) DH5.2(CATHODE) DK1.1(ANODE) DK2.1(ANODE) DL49.1(ANODE) DL50.1(ANODE) DL51.1(ANODE) DL52.1(ANODE) FB22.2 J1.3 J3.6(VSS2) J3.10(GND0) J3.11(GND1) J3.12(GND2) J3.13(GND3) J7.1(GND1) J7.4(GND2) J7.7(GND3) J7.10(GND4) J7.13(GND5) J7.16(GND6) J7.17(GND7) J7.27(GND8) J7.30(GND9) J7.32(GDN10) J7.33(GND11) J7.37(GND12) J7.41(GND13) J7.42(GND14) J9.1(GND1) J9.5(GND2) J9.9(SGND1) J9.10(SGND2) J9.11(SGND3) J9.12(SGND4) J11.9 J11.10 J11.11 J11.12 J11.13 J11.14 J11.19 J12.1 J12.2 J21.5(A) J33.3 J35.1 J36.1 J56.3 J79.5(A) J81.2(GND0) J81.3(GND1) J82.1 J82.2 JH1.2(G_D2) JH1.5(G_D1) JH1.8(G_D0) JH1.11(G_CLK) JH1.17(G_DDC/CEC) JH1.20(SHIELD1) JH1.21(SHIELD2) JH1.22(SHIELD3) JH1.23(SHIELD4) JL6.1(GND) JL6.7 JL6.8 JL26.7(GND1) JL26.8(GND2) JL26.9(GND3) JL26.10(GND4) JL26.C5(GND) KK1.2 KK2.2 KK3.2 KK4.2 KK5.2 KK6.2 KP1.2 OC5.2 OC6.2 QL1.2(E) QL3.2(E) QL5.2(E) QL13.2(E) R24.2 R46.1 R50.2 R184.1 R185.2 R229.2 R239.1 R263.2 R285.2 R292.1 R315.2 R421.2 R423.2 RC9.2 RL15.2 RL39.1 RL44.1 RL55.1 RL69.2 RL85.2 RM2.1 RM18.2 RM22.2 RM24.2 RM26.2 RM29.2 RM31.2 RM35.2 RM36.2 RM38.2 RM40.2 RM55.1 RU13.2 RU14.2 TP5.1(TP) TP6.1(TP) TP7.1(TP) TP8.1(TP) TP9.1(TP) TP10.1(TP) TP11.1(TP) TP12.1(TP) TP62.1(TP) TP82.1(TP) U2.2(GND) U3.2(+) U11.3 U11.9 U11.10 U11.13 U12.1(GND) U12.5(GND1) U12.12(GND2) U13.9(GND) U13.10(GND1) U13.15(GND2) U13.16(GND3) U19.10(GND) U19.15(GND1) U19.16(GND2) U22.19 U22.20 U23.11(GND) U24.2(GND) U27.1(GND) U27.2(GND1) U27.5(GND2) U27.10(GND3) U27.14(GND4) U27.37(GND6) U27.40(GND7) U27.41(GND8) U27.43(GND9) U27.57(GND10) U27.58(GND11) U27.60(GND12) U27.61(GND13) U27.64(GND14) U27.65(GND15) U27.77(GND16) U27.78(GND17) U27.80(GND18) U27.81(GND5) U32.15(GND) U39.2(GND) U51.5(GND) U51.10(NOE) U901.41(GND6) U901.42(GND7) U901.43(GND8) U901.44(GND9) U901.45(GND10) U901.46(GND11) U901.47(GND12) U901.87(GND13) U901.109(GND15) U901.110(GND16) U901.111(GND17) U901.112(GND18) U901.113(GND19) U901.114(GND20) U901.115(GND21) U901.122(GND22) U901.135(GND23) U901.146(GND24) U902.4(NC) U902.8(GNDIO) U902.9(GND) UH1.3(GND1) UH1.8(GND2) UH2.3(GND1) UH2.8(GND2) UL9.2(GND) UM1.41(EGND) UM2.1 UM2.3 UM2.5 UM2.7 UM2.9 UM2.11 UM2.14 UM2.24 UM2.26 UM2.28 UM2.30 UM2.32 UM2.34 USB1.5(GND) USB1.6 USB1.7 USB1.8 USB1.9 USB1.10 USB1.11 UU3.2(GND) X3.2(GND1) X3.4(GND2) Y3.2 Y3.4
GND_SIGNAL: ANT3.1(CENTER2) ANT3.2(SHIELD2) CG1.1 CG2.1 CG3.1 FB22.1 U8.10(GND1) U8.12(GND2) U8.13(GND3) U8.24(GND4)
VBAT: C69.2 C70.2 J1.1 J11.5 J11.7 U901.30(VBAT1) U901.31(VBAT2)
VCC33-AUDIO: C196.1 C469.1 FB12.2 R183.1 U23.7(PVDD)
VCC-1V8: C302.2 C304.2 C460.2 C461.2 J7.18(VCC1-1V8) J7.19(VCC2-1V8) TP63.1(TP) U24.5(VOUT)
VCC-3V3: C114.2 C115.2 C116.2 C117.2 C163.2 C167.1 C194.1 C195.1 C209.2 C303.2 C313.2 C314.2 C328.1 C459.2 C466.1 DH12.1 DL6.1(ANODE) DL7.1(ANODE) FB12.1 J11.6 J11.8 J36.2 J80.1 Q2.1(G) R13.2 R39.1 R40.1 R41.1 R75.2 R76.2 R192.1 R237.1 R238.1 R241.2 R420.2 R531.2 R532.2 R533.2 R550.1 RC1.1 RG1.2 RG2.2 RL12.1 RL57.1 RM4.2 RM7.2 RM53.2 RP82.2 RP84.2 U11.14 U12.13(VCC) U12.14(VCC1) U24.1(VIN) U32.16(DVDD) U32.24(V33) U51.1(VCC) U901.50(3V3_1) U901.51(3V3_2) U902.7(VDD) UM2.20 UM2.21 UM2.22 UM2.23
VCC-5V: C181.1 C182.2 C184.2 C457.2 C458.2 C471.2 C472.2 CH2.1 CL60.1 CL65.1 CU2.2 J11.1 J11.3 JH1.18(+5V) R548.1 RH17.1 RH18.1 RU12.1 U11.8 U22.1 U901.33(ACIN1) U901.34(ACIN2) UL9.5(IN) USB1.1(VBUS) UU3.5(IN)
VCC-PE: RP82.1 RP85.1 U22.3
VCC-RTC: C84.2 C385.2 D608.2 J11.20 U901.32(RTC)
VCC-WIFI-IO: C170.1 C467.1 RP81.1 U13.14(IOVCC)
4G-STATUS: U27.49(STATUS) U901.105(4G_STATUS)
ALDO1: CL47.2 CL58.2 CL59.2 J11.16 RK1.2 RK8.2 U27.15(VDD_1V8) U901.38(ALDO1)
ALDO3: C210.2 CL13.1 J11.17 J35.2 JL6.4(VDD) Q23.1(G) R77.2 R78.2 U901.39(ALDO3) U902.3(VDIO)
ANT-BIAS: CG1.2 U8.9(ANT_BIAS)
AP-WAKE-4G: U27.72(DTR) U901.108(AP_WAKE_4G)
AP-WAKE-BT: R528.2 U13.13(AP-WAKE-BT) U901.155(AP_WAKE_BT)
AUDIO-L: D609.2(CATHODE) J79.4(D) R180.2
AUDIO-R: D610.2(CATHODE) J79.2(B) R181.1
AVDUSB: RP75.2 U8.7(AVDUSB)
BATT-VCC-3V3: C85.2 D7.2 R43.2 U2.1(VIN) U3.1(-)
BATT-VCC-RTC: C81.2 C82.2 D608.1 R45.2 U2.5(VOUT)
BB-PWREN: RL70.2 U901.107(BB_PWREN)
BB_PW: RL38.2 U901.121(BB_PW)
BLDO1: J11.18 RP81.2 RP85.2 U901.40(BLDO1)
BT-RST-N: R526.2 U13.12(BT-RST-N) U901.156(BT_RST_N)
BT-UART-CTS: U13.6(CTS) U901.1(BT_UART_CTS)
BT-UART-RTS: R525.2 U13.8(RTS) U901.2(BT_UART_RTS)
BT-UART-RX: U13.2(RX) U901.9(BT_UART_RX)
BT-UART-TX: U13.4(TX) U901.8(BT_UART_TX)
BT-WAKE-AP: U13.11(BT-WAKE-AP) U901.120(BT_WAJE_AP)
CLKOUT-125M: RM14.1 UM1.35(CLKOUT)
CSI0-D0: R434.2 U22.11
CSI0-D1: R435.2 U22.12
CSI0-D2: R436.2 U22.13
CSI0-D3: R437.2 U22.14
CSI0-D4: R438.2 U22.15
CSI0-D5: R439.2 U22.16
CSI0-D6: R440.2 U22.17
CSI0-D7: R441.2 U22.18
CSI0-HSYNC: R432.2 U22.9
CSI0-MCLK: C456.1 R431.2 U22.10
CSI0-PCLK: R430.2 U22.5
CSI0-PWR: R522.2 U22.2
CSI0-RSET: R442.2 U22.4
CSI0-SCK: U22.6 U901.28(CSI0_SCK)
CSI0-SDA: U22.7 U901.27(CSI0_SDA)
CSI0-VSYNC: R433.2 U22.8
CTP-INT: C464.2 JL6.2(INT) U901.117(CTP_INT)
CTP-RST: C465.2 JL6.3(RST/WAKE) R533.1 U901.116(CTP_RST)
DC1SW: C111.1 C112.1 C462.2 C463.2 J7.38(VDD1) J7.39(VDD2) J11.15 J82.18 J82.20 R269.2 R320.2 RL47.2 TP66.1(TP) U901.37(VCC_LCD)
DM1_USB: U27.12(USB_DN) U32.27(DM1)
DM2_USB: D28.1(ANODE) J9.3(1D-) U32.2(DM2)
DM3_USB: D29.1(ANODE) J9.7(2D-) U32.8(DM3)
DM4_USB: TP87.1(TP) U32.11(DM4)
DP1_USB: U27.13(USB_DP) U32.28(DP1)
DP2_USB: D27.1(ANODE) J9.2(1D+) U32.3(DP2)
DP3_USB: D30.1(ANODE) J9.6(2D+) U32.9(DP3)
DP4_USB: TP88.1(TP) U32.12(DP4)
EPHY-CLK-25M: RM56.2 U901.24(EPHY_CLK_25M)
FEL: RK7.2 U901.95(FEL)
GPADC0: CK1.2 DK1.2(CATHODE) J33.1 RK1.1 RK2.2 U901.97(GPADC0)
GPADC1: CK16.2 DK2.2(CATHODE) J33.2 RK8.1 U901.96(GPADC1)
GPS-RESETN: R529.2 U8.8(PRRSTX) U901.57(GPS_RST)
HCEC: RH21.1 U901.133(HCEC)
HDMI-CEC: DH5.1(ANODE) JH1.13(CEC) RH16.2 RH21.2
HDMI-SCL: DH4.1(ANODE) JH1.15(SCL) RH17.2 RH19.2
HDMI-SDA: DH3.1(ANODE) JH1.16(SDA) RH18.2 RH20.2
HHPD: CH1.1 RH5.1 U901.134(HHPD)
HSCL: RH19.1 U901.131(HSCL)
HSDA: RH20.1 U901.132(HSDA)
HTX0N: JH1.9(D0N) U901.125(HTX0N) UH2.2(IN2) UH2.9(OUT2)
HTX0P: JH1.7(D0P) U901.126(HTX0P) UH2.1(IN1) UH2.10(OUT1)
HTX1N: JH1.6(D1N) U901.127(HTX1N) UH1.5(IN4) UH1.6(OUT4)
HTX1P: JH1.4(D1P) U901.128(HTX1P) UH1.4(IN3) UH1.7(OUT3)
HTX2N: JH1.3(D2N) U901.129(HTX2N) UH1.2(IN2) UH1.9(OUT2)
HTX2P: JH1.1(D2P) U901.130(HTX2P) UH1.1(IN1) UH1.10(OUT1)
HTXCN: JH1.12(CLKN) U901.123(HTXCN) UH2.5(IN4) UH2.6(OUT4)
HTXCP: JH1.10(CLKP) U901.124(HTXCP) UH2.4(IN3) UH2.7(OUT3)
I2S2-BCLK: R527.1 U11.6
I2S2-DIN: R528.1 U11.7
I2S2-DOUT: R529.1 U11.12
I2S2-LRCK: R526.1 U11.5
I2S2-MCLK: R525.1 U11.4
INTB: RM20.1 UM1.31(INTB/PMEB)
LCD-CLK: J82.7 U901.70(LCD_CLK)
LCD-D3: J82.9 U901.58(LCD_D3)
LCD-D4: J82.10 U901.68(LCD_D4)
LCD-D5: J82.11 U901.63(LCD_D5)
LCD-D6: J82.12 U901.67(LCD_D6)
LCD-D7: J82.13 U901.66(LCD_D7)
LCD-D10: J82.14 U901.64(LCD_D10)
LCD-D11: J82.15 U901.69(LCD_D11)
LCD-D12: J82.16 U901.60(LCD_D12)
LCD-D13: J82.3 R342.1 U901.59(LCD_D13)
LCD-D14: J82.5 RL47.1 U901.62(LCD_D14)
LCD-D18: R286.2 U901.65(LCD_D18)
LCD-D19: J82.17 U901.61(LCD_D19)
LCD-DC-EN-1: R285.1 R286.1 U39.4(EN)
LCD-DE: J82.6 U901.73(LCD_DE)
LCD-HSYNC: J82.8 U901.72(LCD_HSYNC)
LCD-PWM: R319.1 R320.1 RL48.1 U901.74(LCD_PWM)
LCD-RST: R342.2 RL32.1 RL55.2
LCD-RST-1: CL19.1 J7.24(RSTB) RL32.2 RL44.2 TP65.1(TP)
LCD-VSYNC: J82.4 U901.71(LCD_VSYNC)
LED0/CFG-EXT: CM15.2 RM26.1 RM27.2 RM28.2 RM33.2 UM1.32(LED0/CFG_EXT)
LED1/CFG-LDO0: CM24.2 RM29.1 RM30.2 TP85.1(TP) U19.14(Y+) UM1.33(LED1/CFG_LDO0)
LED2/CFG-LDO1: CM23.2 RM31.1 RM32.2 TP86.1(TP) U19.11(G+) UM1.34(LED2/CFG_LDO1)
LED-: J82.19 RL49.2
LED-REC: RL12.2 RL13.2 RL14.2 U901.54(LED_REC)
LINEINL: C75.1 U901.93(LINEINL)
LINEINR: C384.1 U901.94(LINEINR)
LINEOUTL: C183.2 U901.91(LINEOUTL)
LINEOUTR: C470.1 U901.92(LINEOUTR)
MBIAS: C49.1 R19.2 U901.88(MBIAS)
MDC: RM8.1 UM1.13(MDC)
MDI0+: TP77.1(TP) U19.2(TD0+) UM1.1(MDI[0]+)
MDI0-: TP78.1(TP) U19.3(TD0-) UM1.2(MDI[0]-)
MDI1+: TP76.1(TP) U19.4(TD1+) UM1.4(MDI[1]+)
MDI1-: TP75.1(TP) U19.7(TD1-) UM1.5(MDI[1]-)
MDI2+: TP74.1(TP) U19.5(TD2+) UM1.6(MDI[2]+)
MDI2-: TP73.1(TP) U19.6(TD2-) UM1.7(MDI[2]-)
MDI3+: TP72.1(TP) U19.8(TD3+) UM1.9(MDI[3]+)
MDI3-: TP71.1(TP) U19.9(TD3-) UM1.10(MDI[3]-)
MDIO: RM9.1 RM16.1 UM1.14(MDIO)
MIC1N-MIC: C58.1 C88.1 C89.2 D10.2(CATHODE) MIC1.2(-) R23.2
MIC1P-MIC: C52.1 C83.1 C88.2 D35.2(CATHODE) MIC1.1(+) R20.2
MICIN1N: C58.2 U901.90(MICIN1N)
